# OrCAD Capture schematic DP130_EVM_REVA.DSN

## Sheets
1 S01_COVER_PAGE
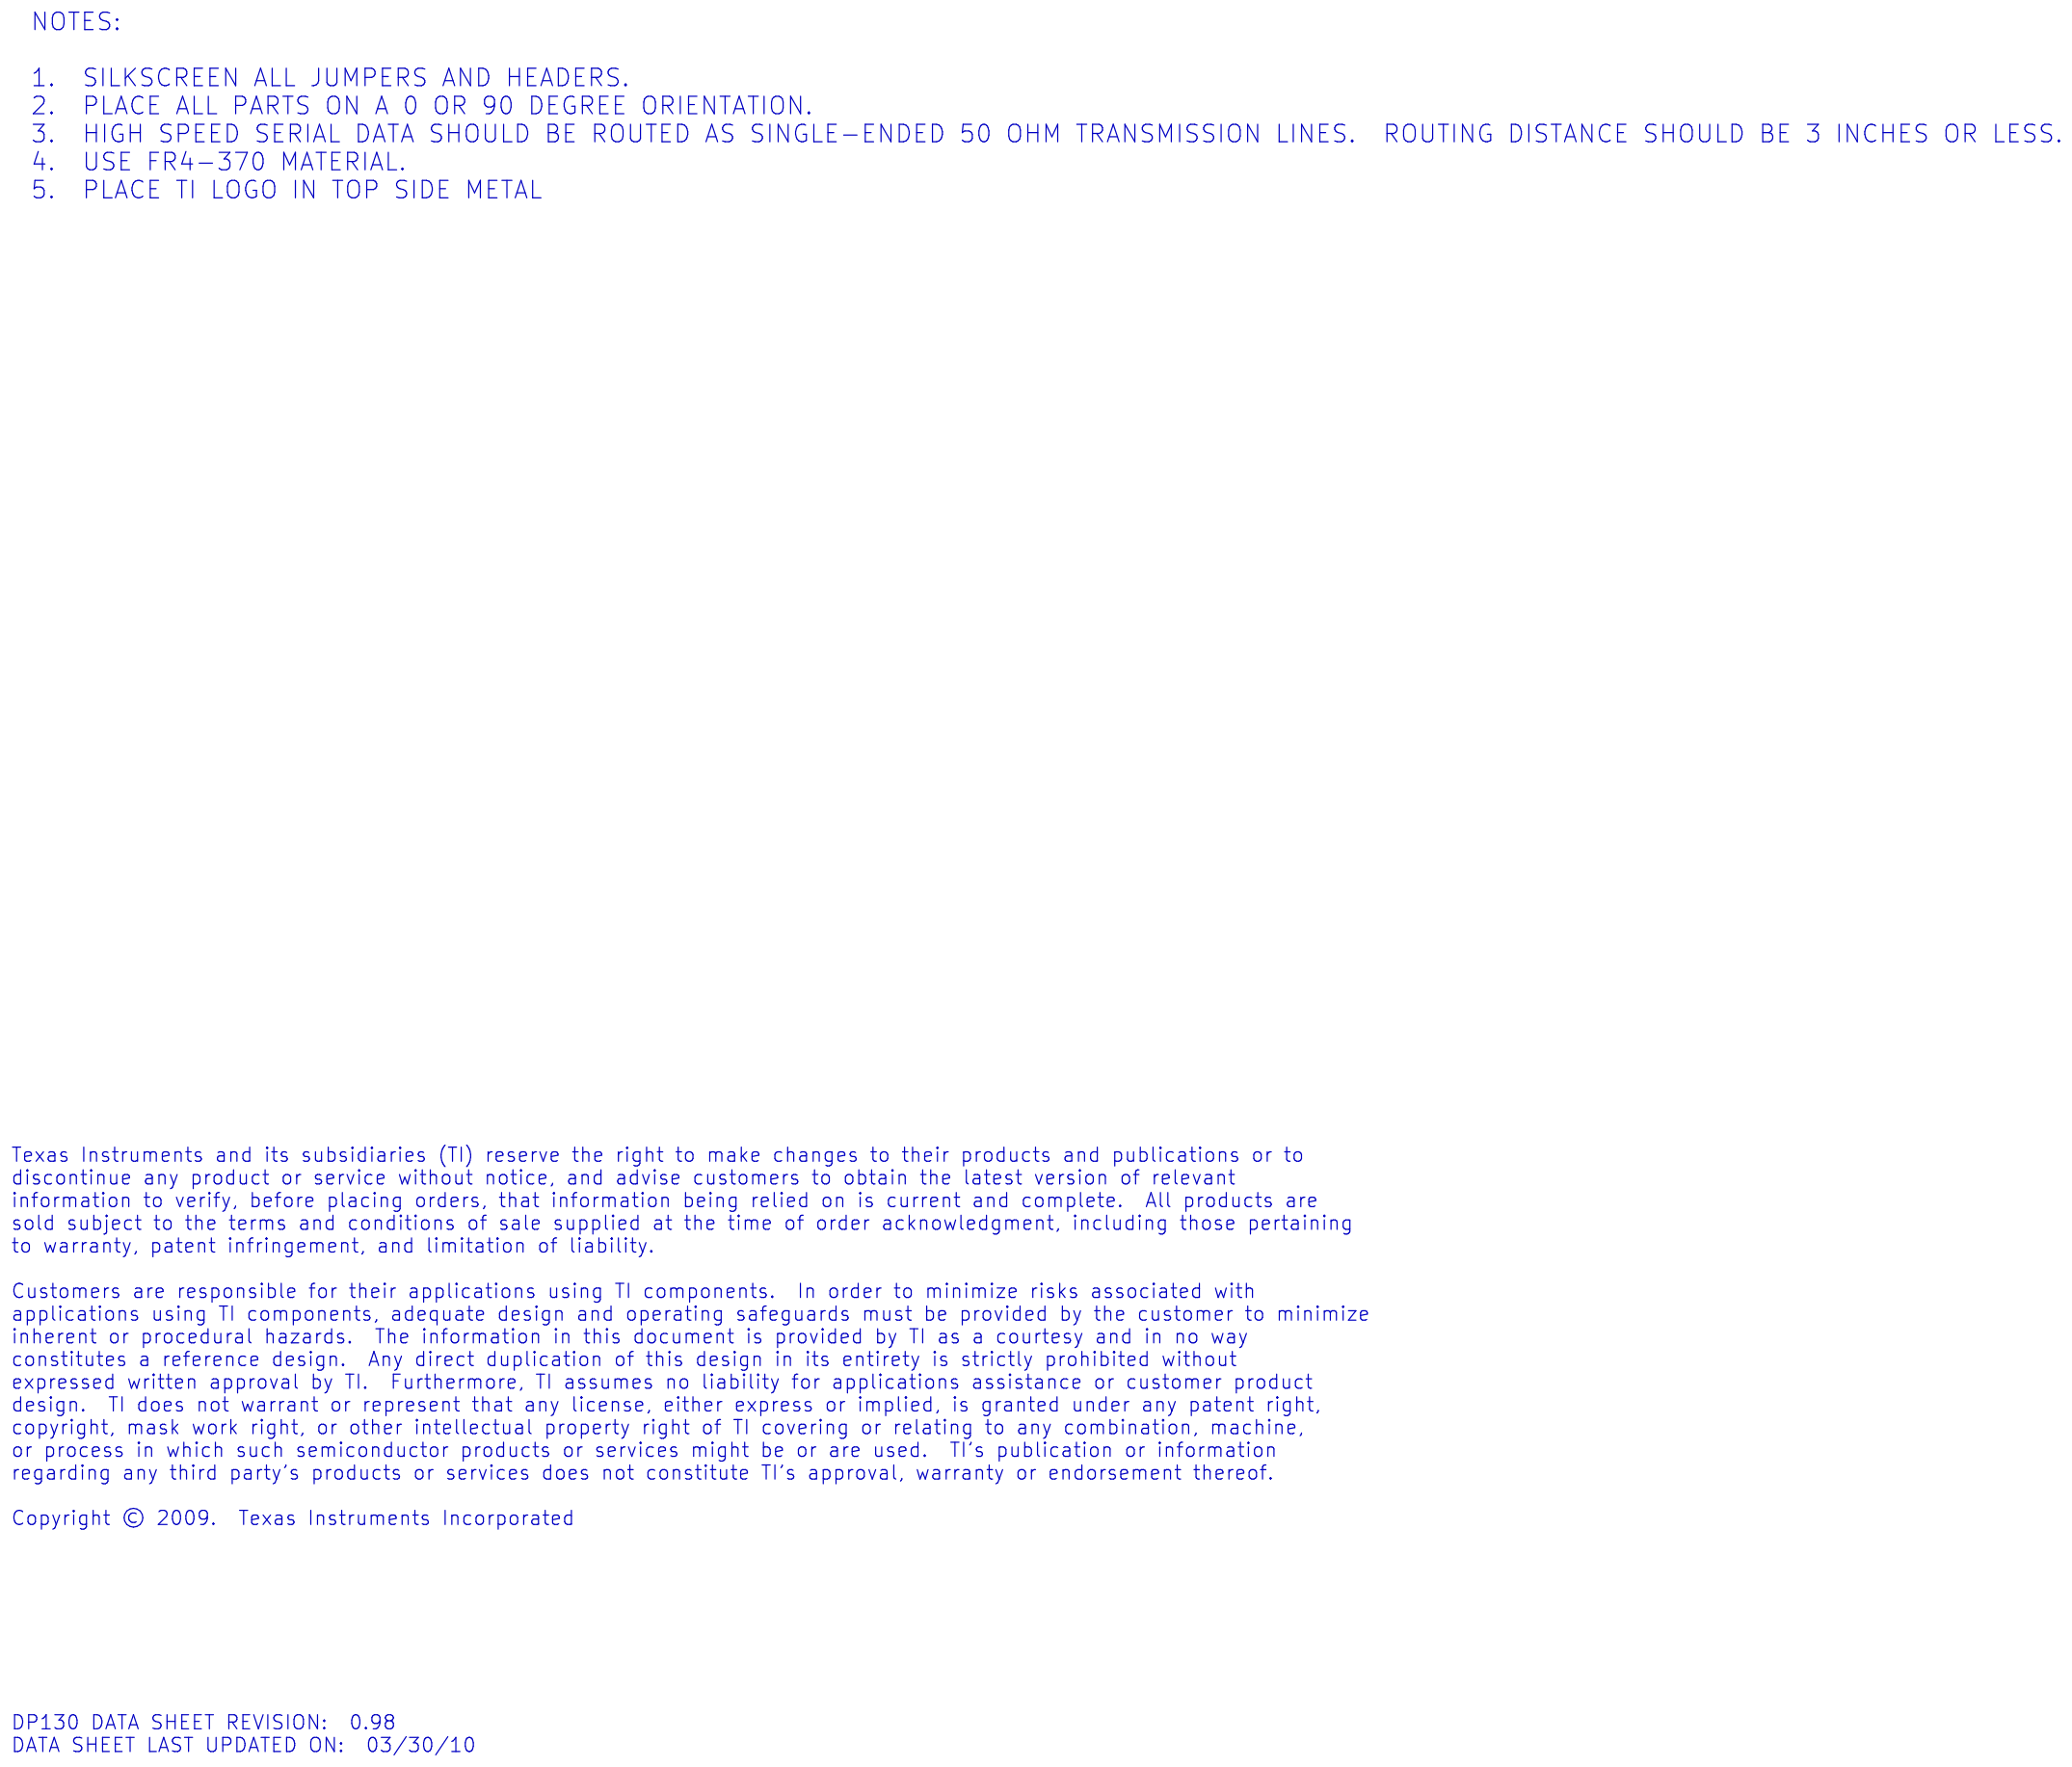
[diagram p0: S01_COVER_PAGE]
2 S02_SOURCE_Connect: size B; note: 6516396
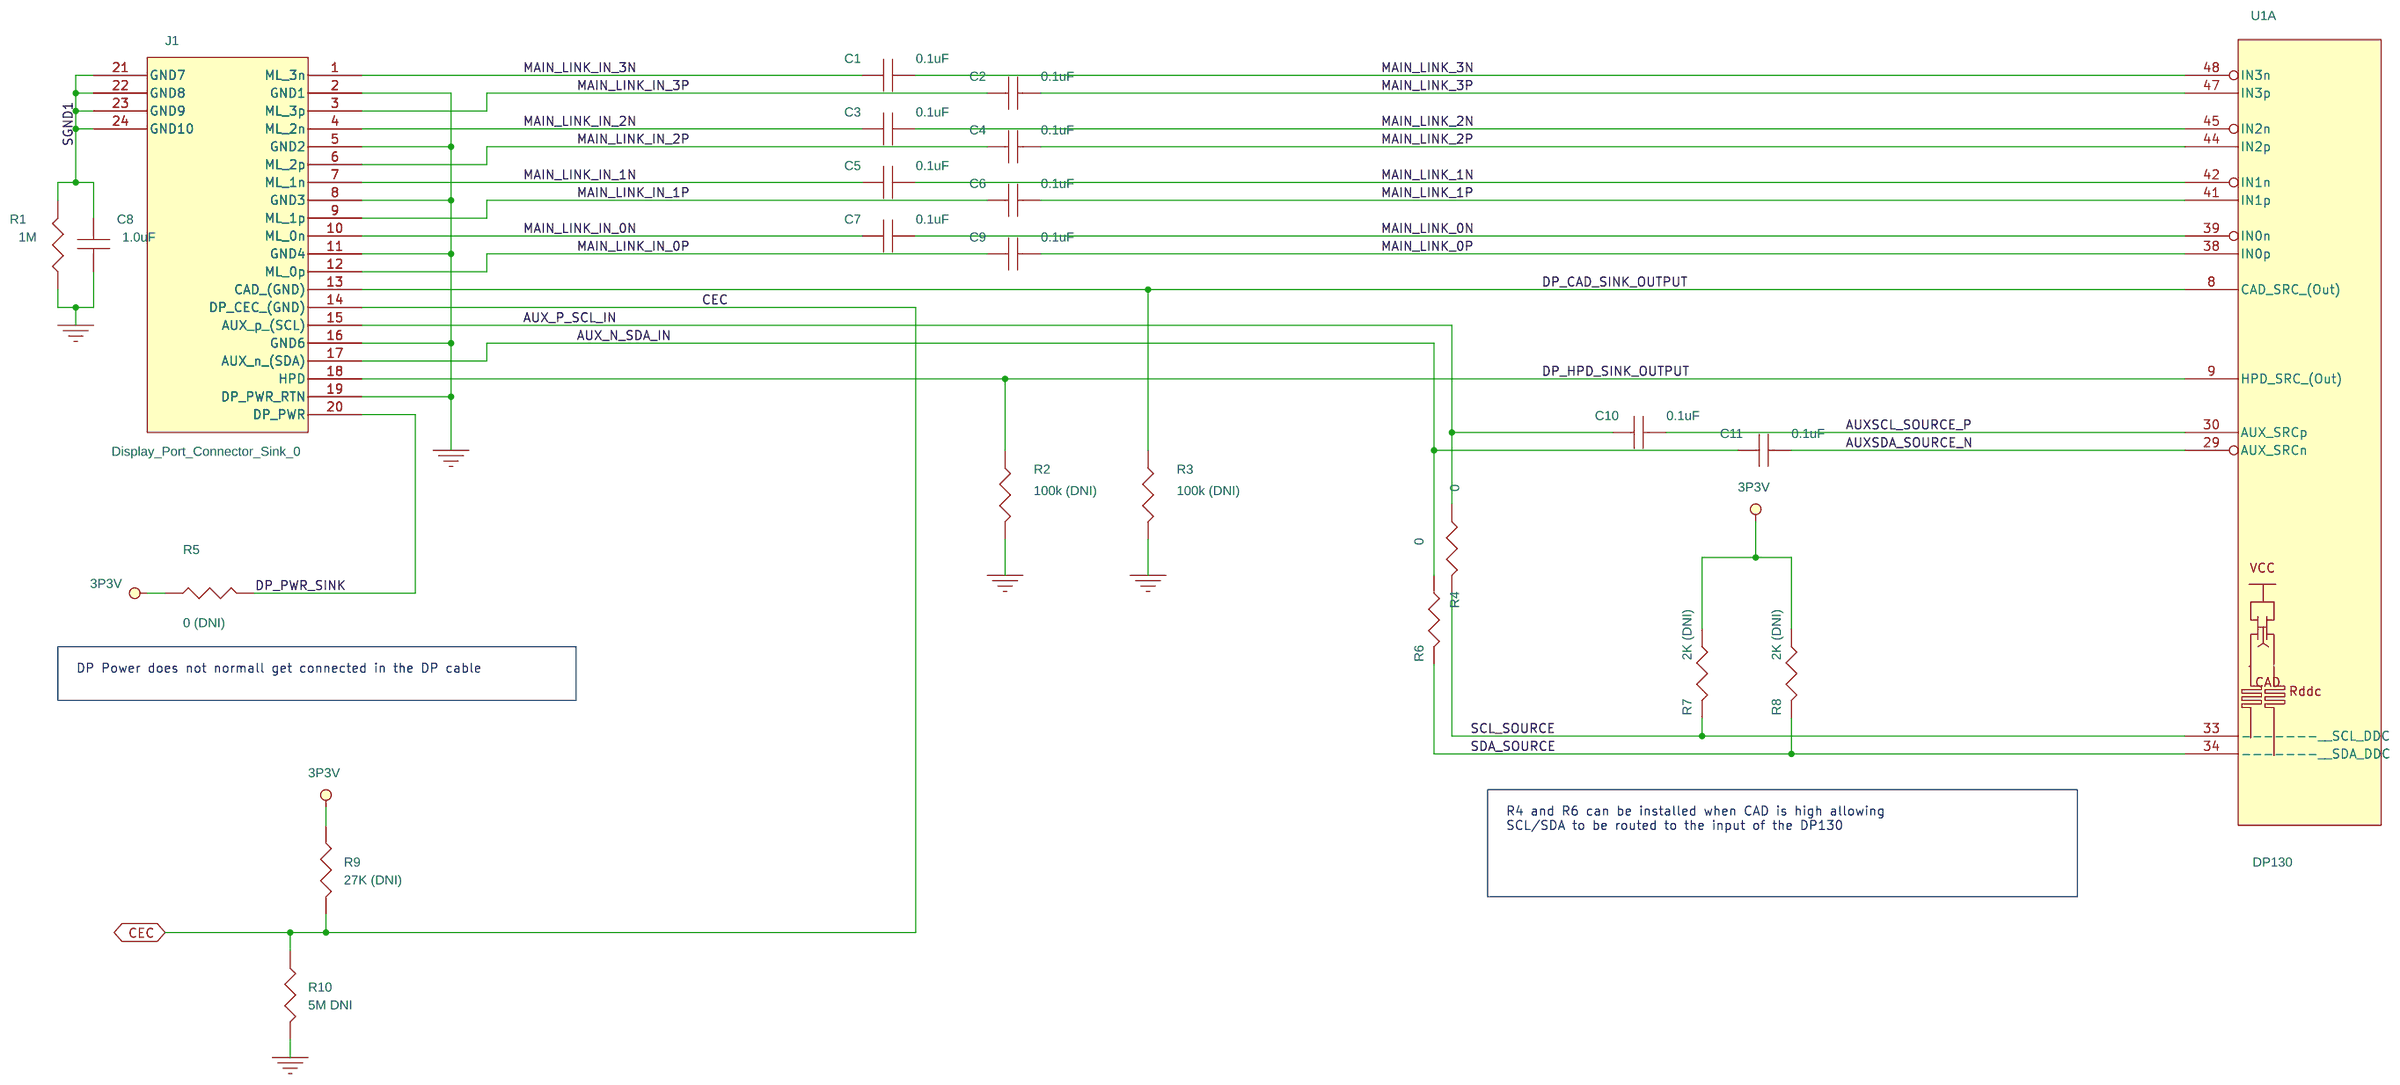
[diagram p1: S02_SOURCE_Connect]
3 S03_SINK_Connect: size B; note: 6516396
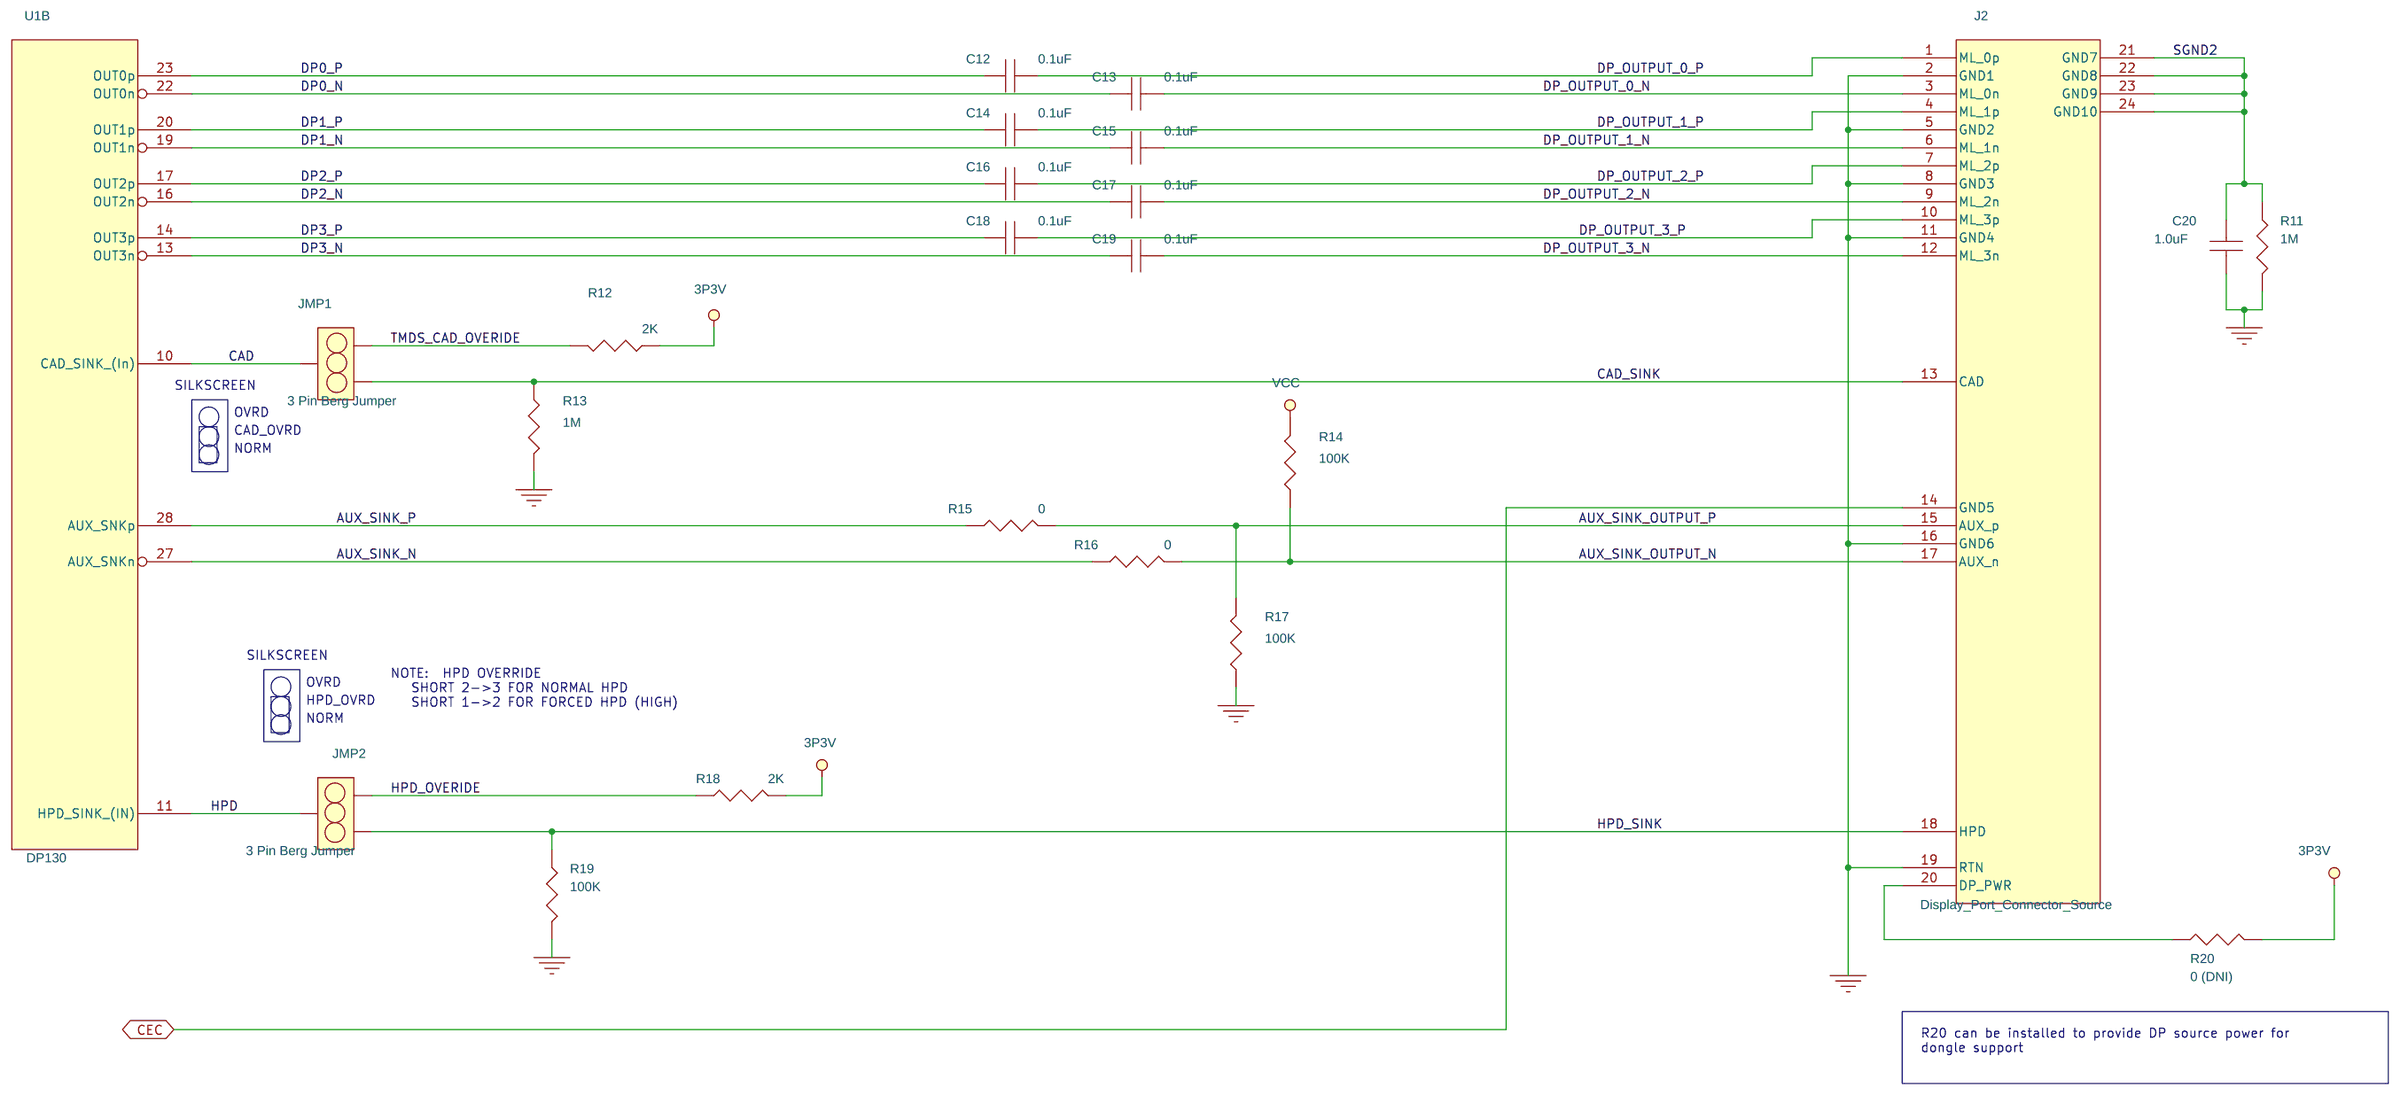
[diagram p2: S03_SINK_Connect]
4 S04_CONTROL: size B; note: 6516396
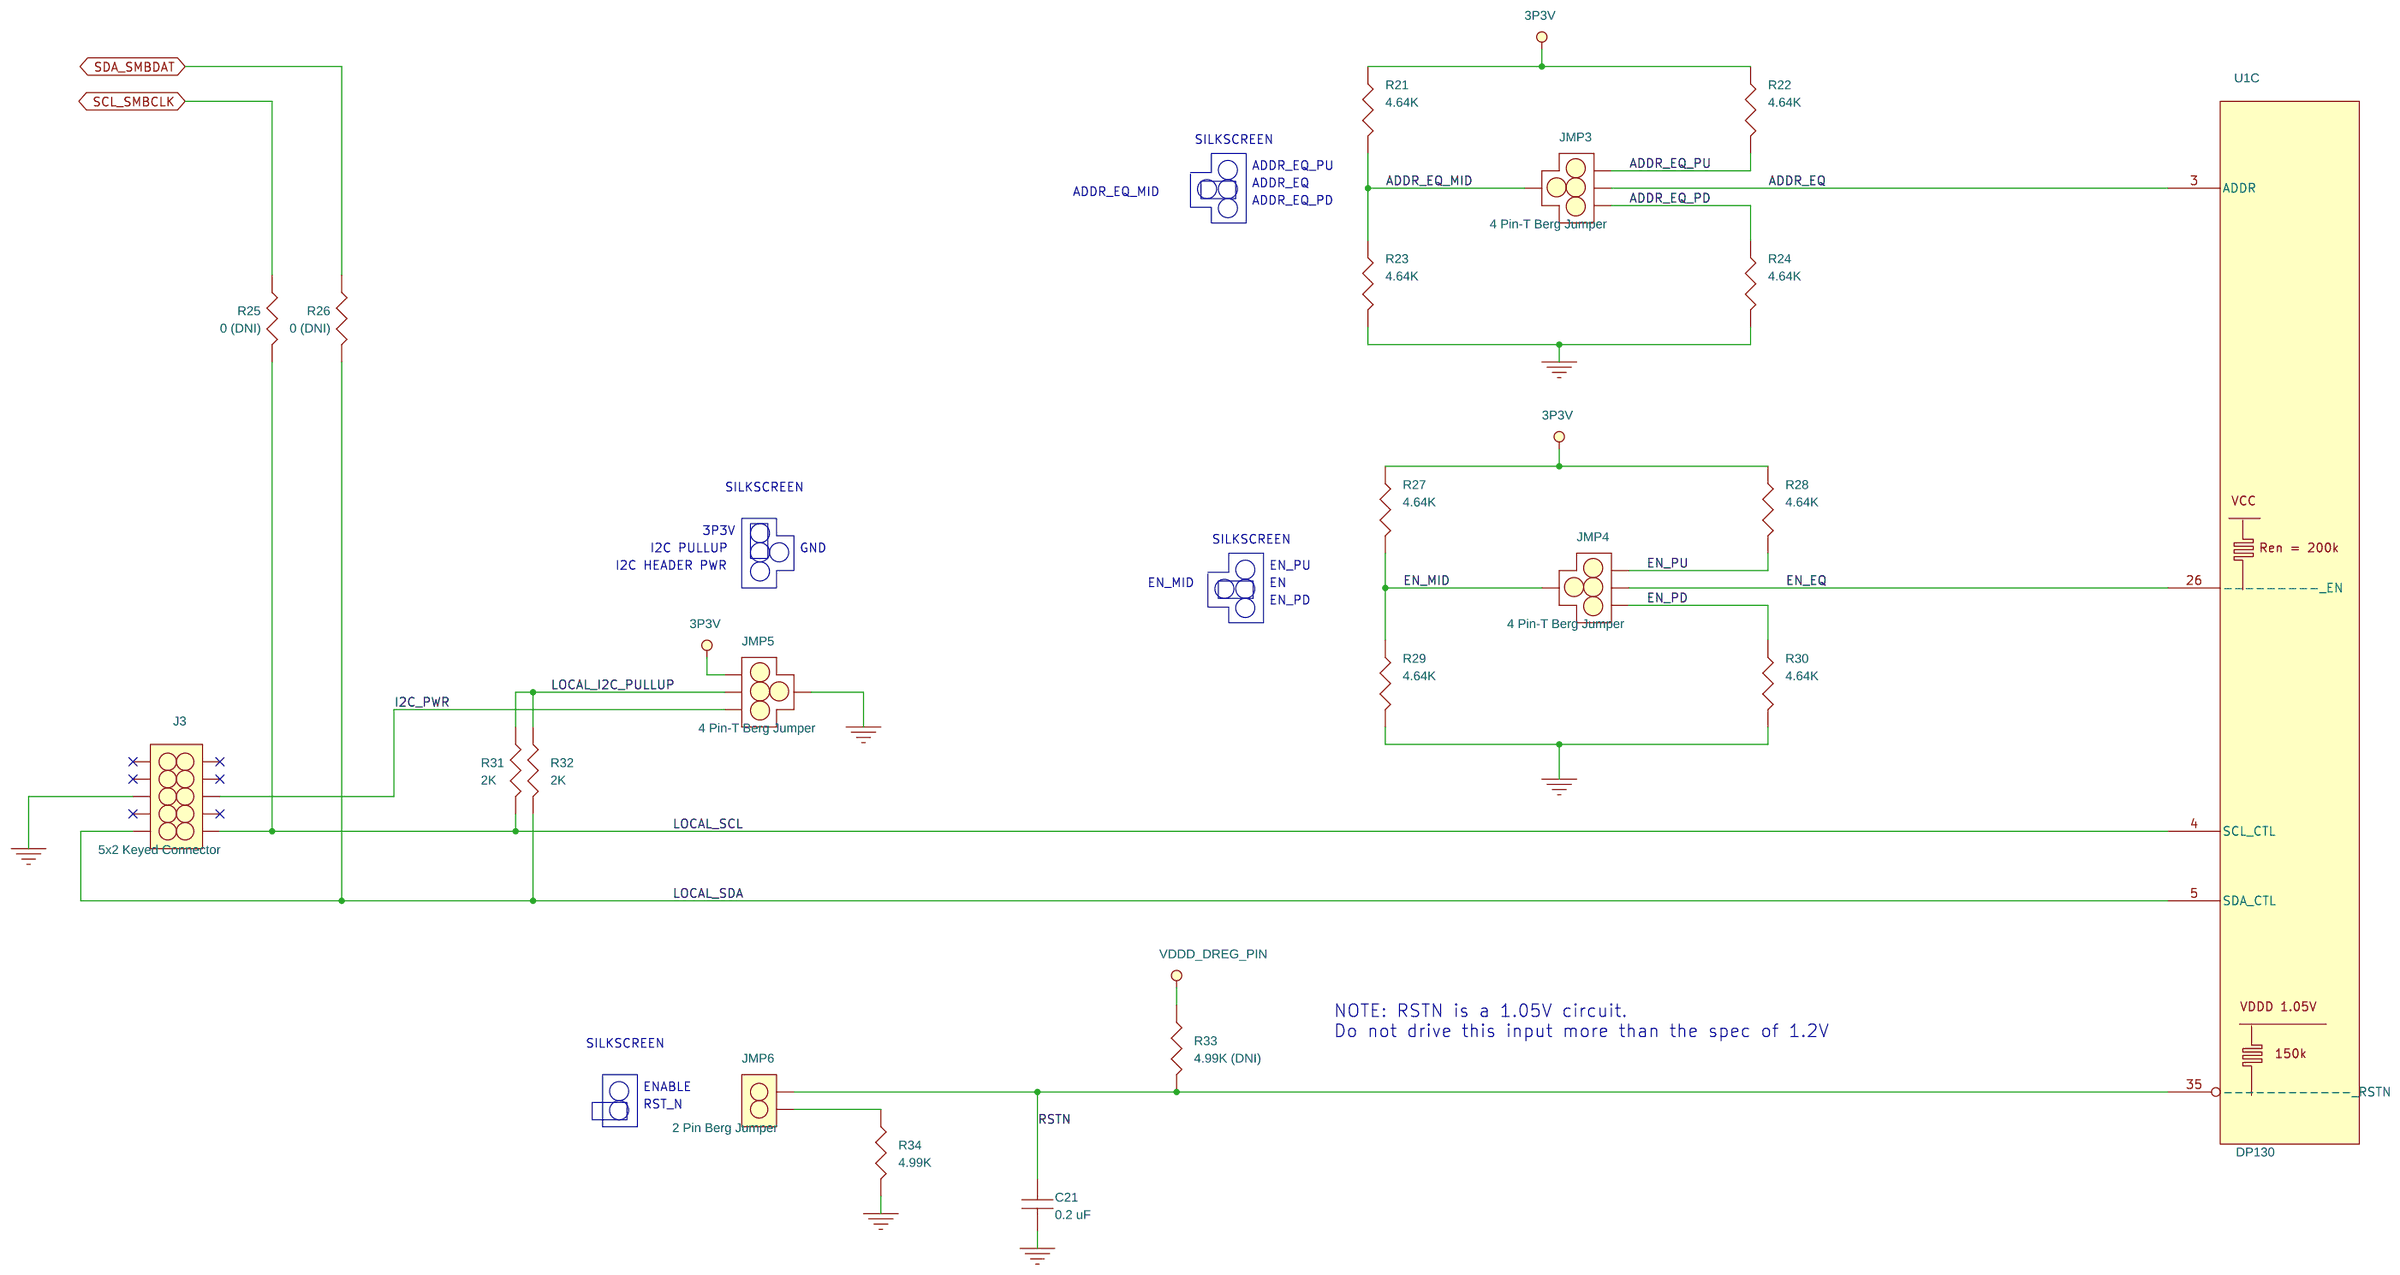
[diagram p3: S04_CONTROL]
5 S05_DEVICE_PWR: size B; note: 6516396
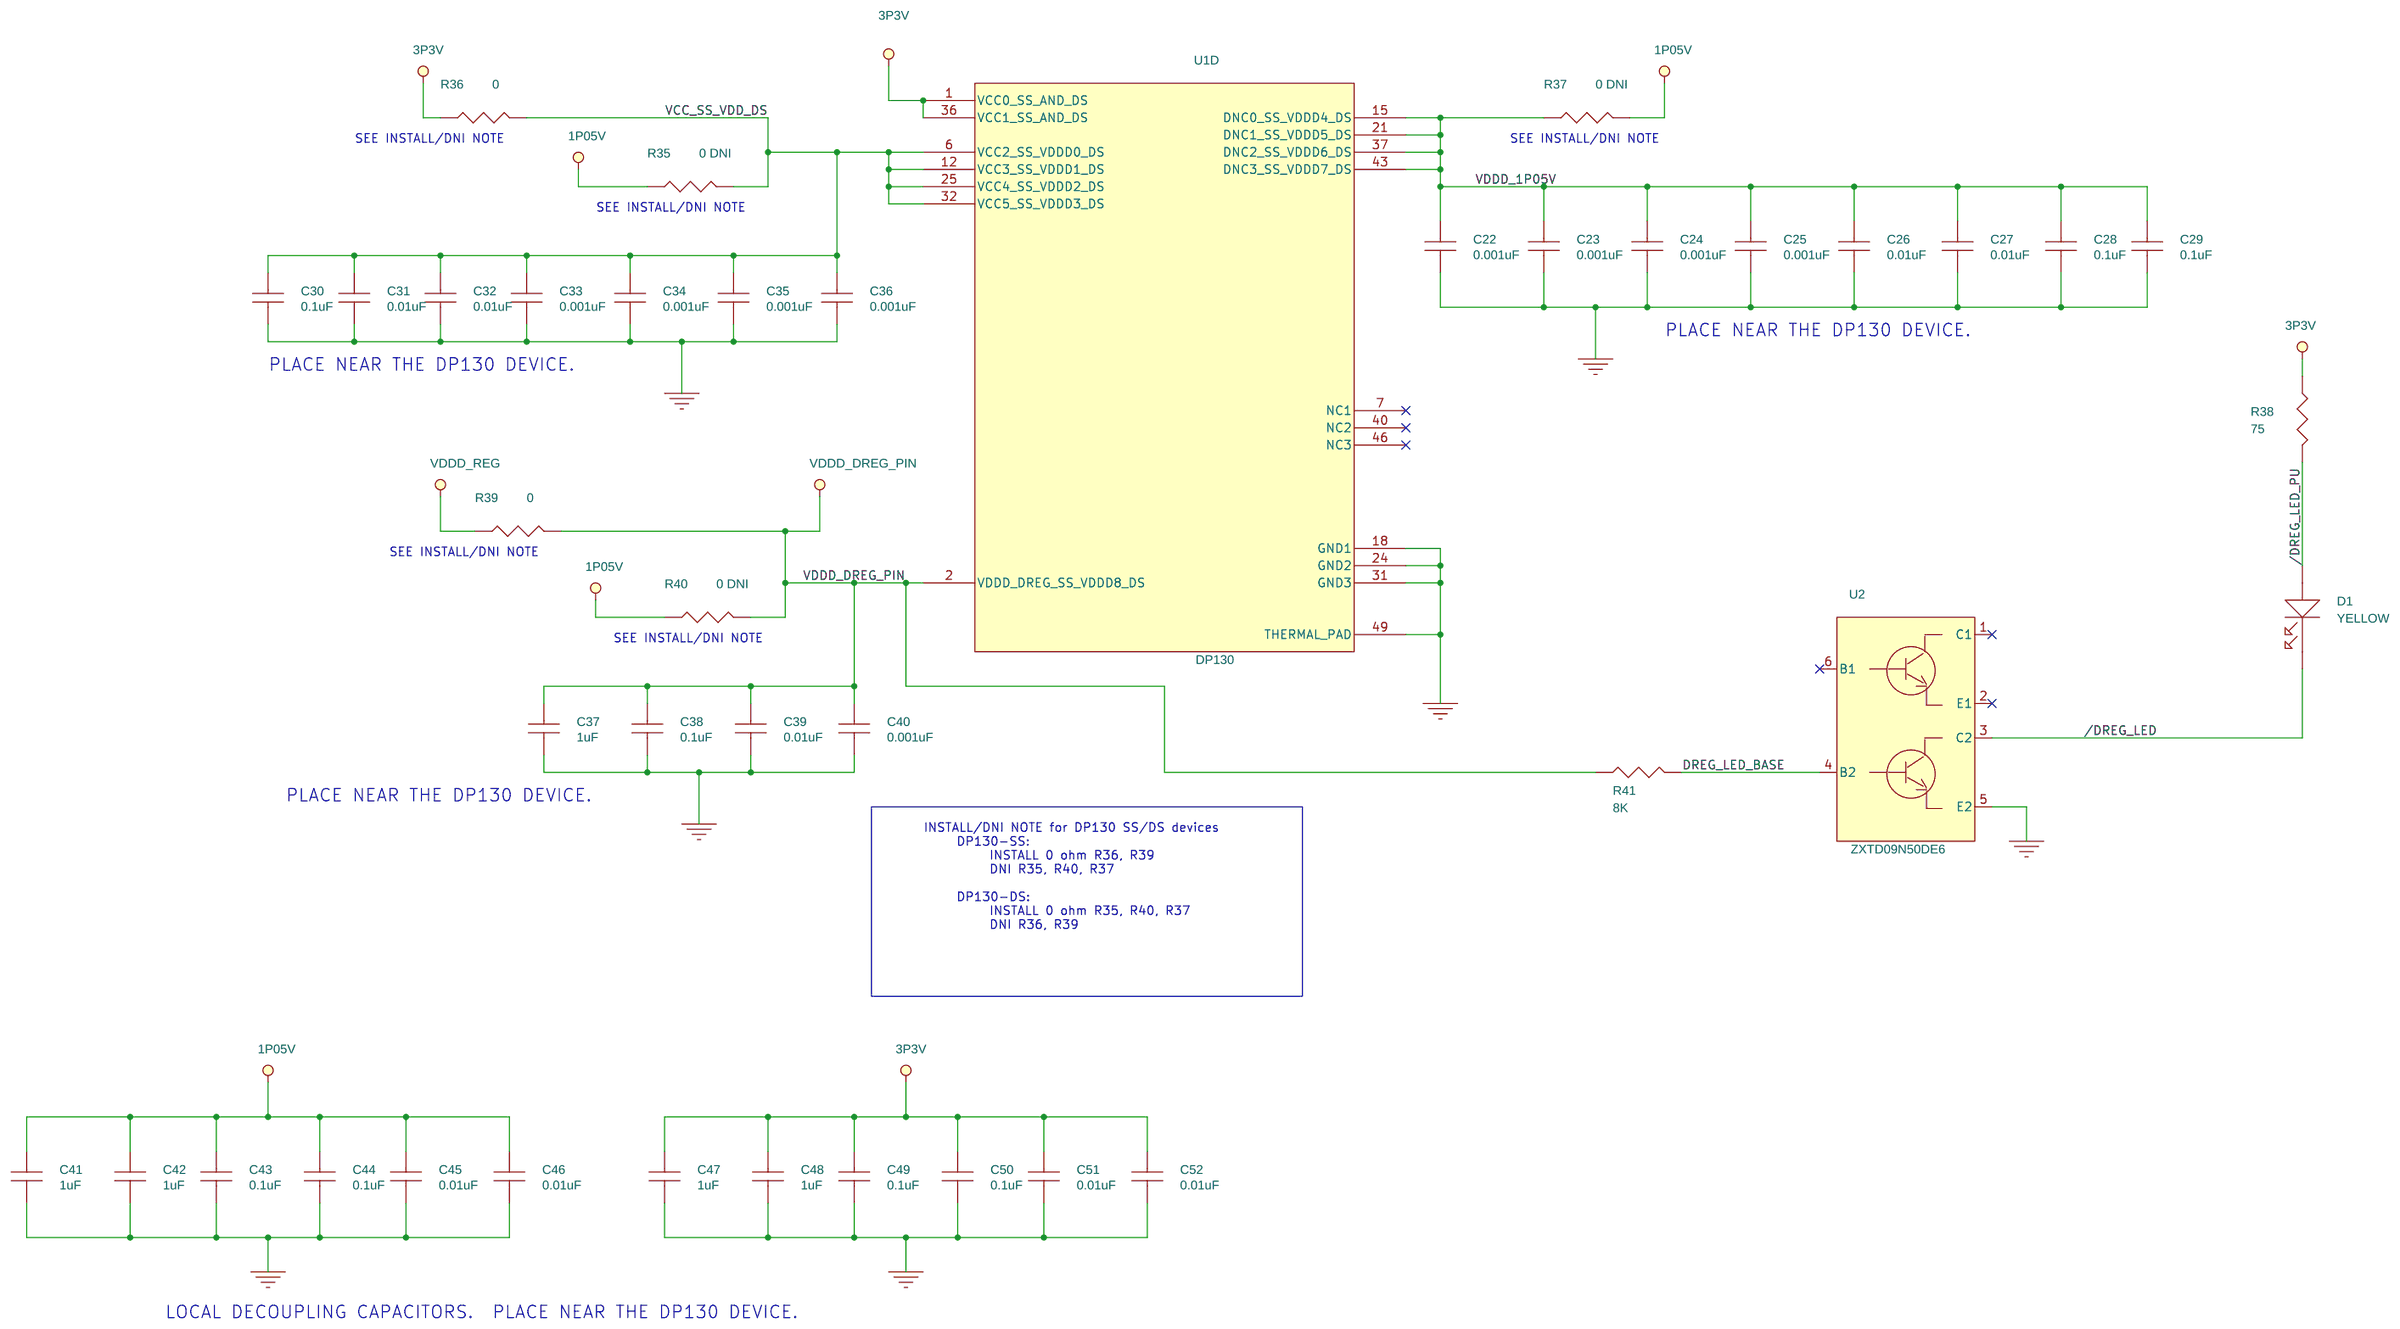
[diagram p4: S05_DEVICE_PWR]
6 S06_EXT_PWR_INTRFC: size B; note: 6516396
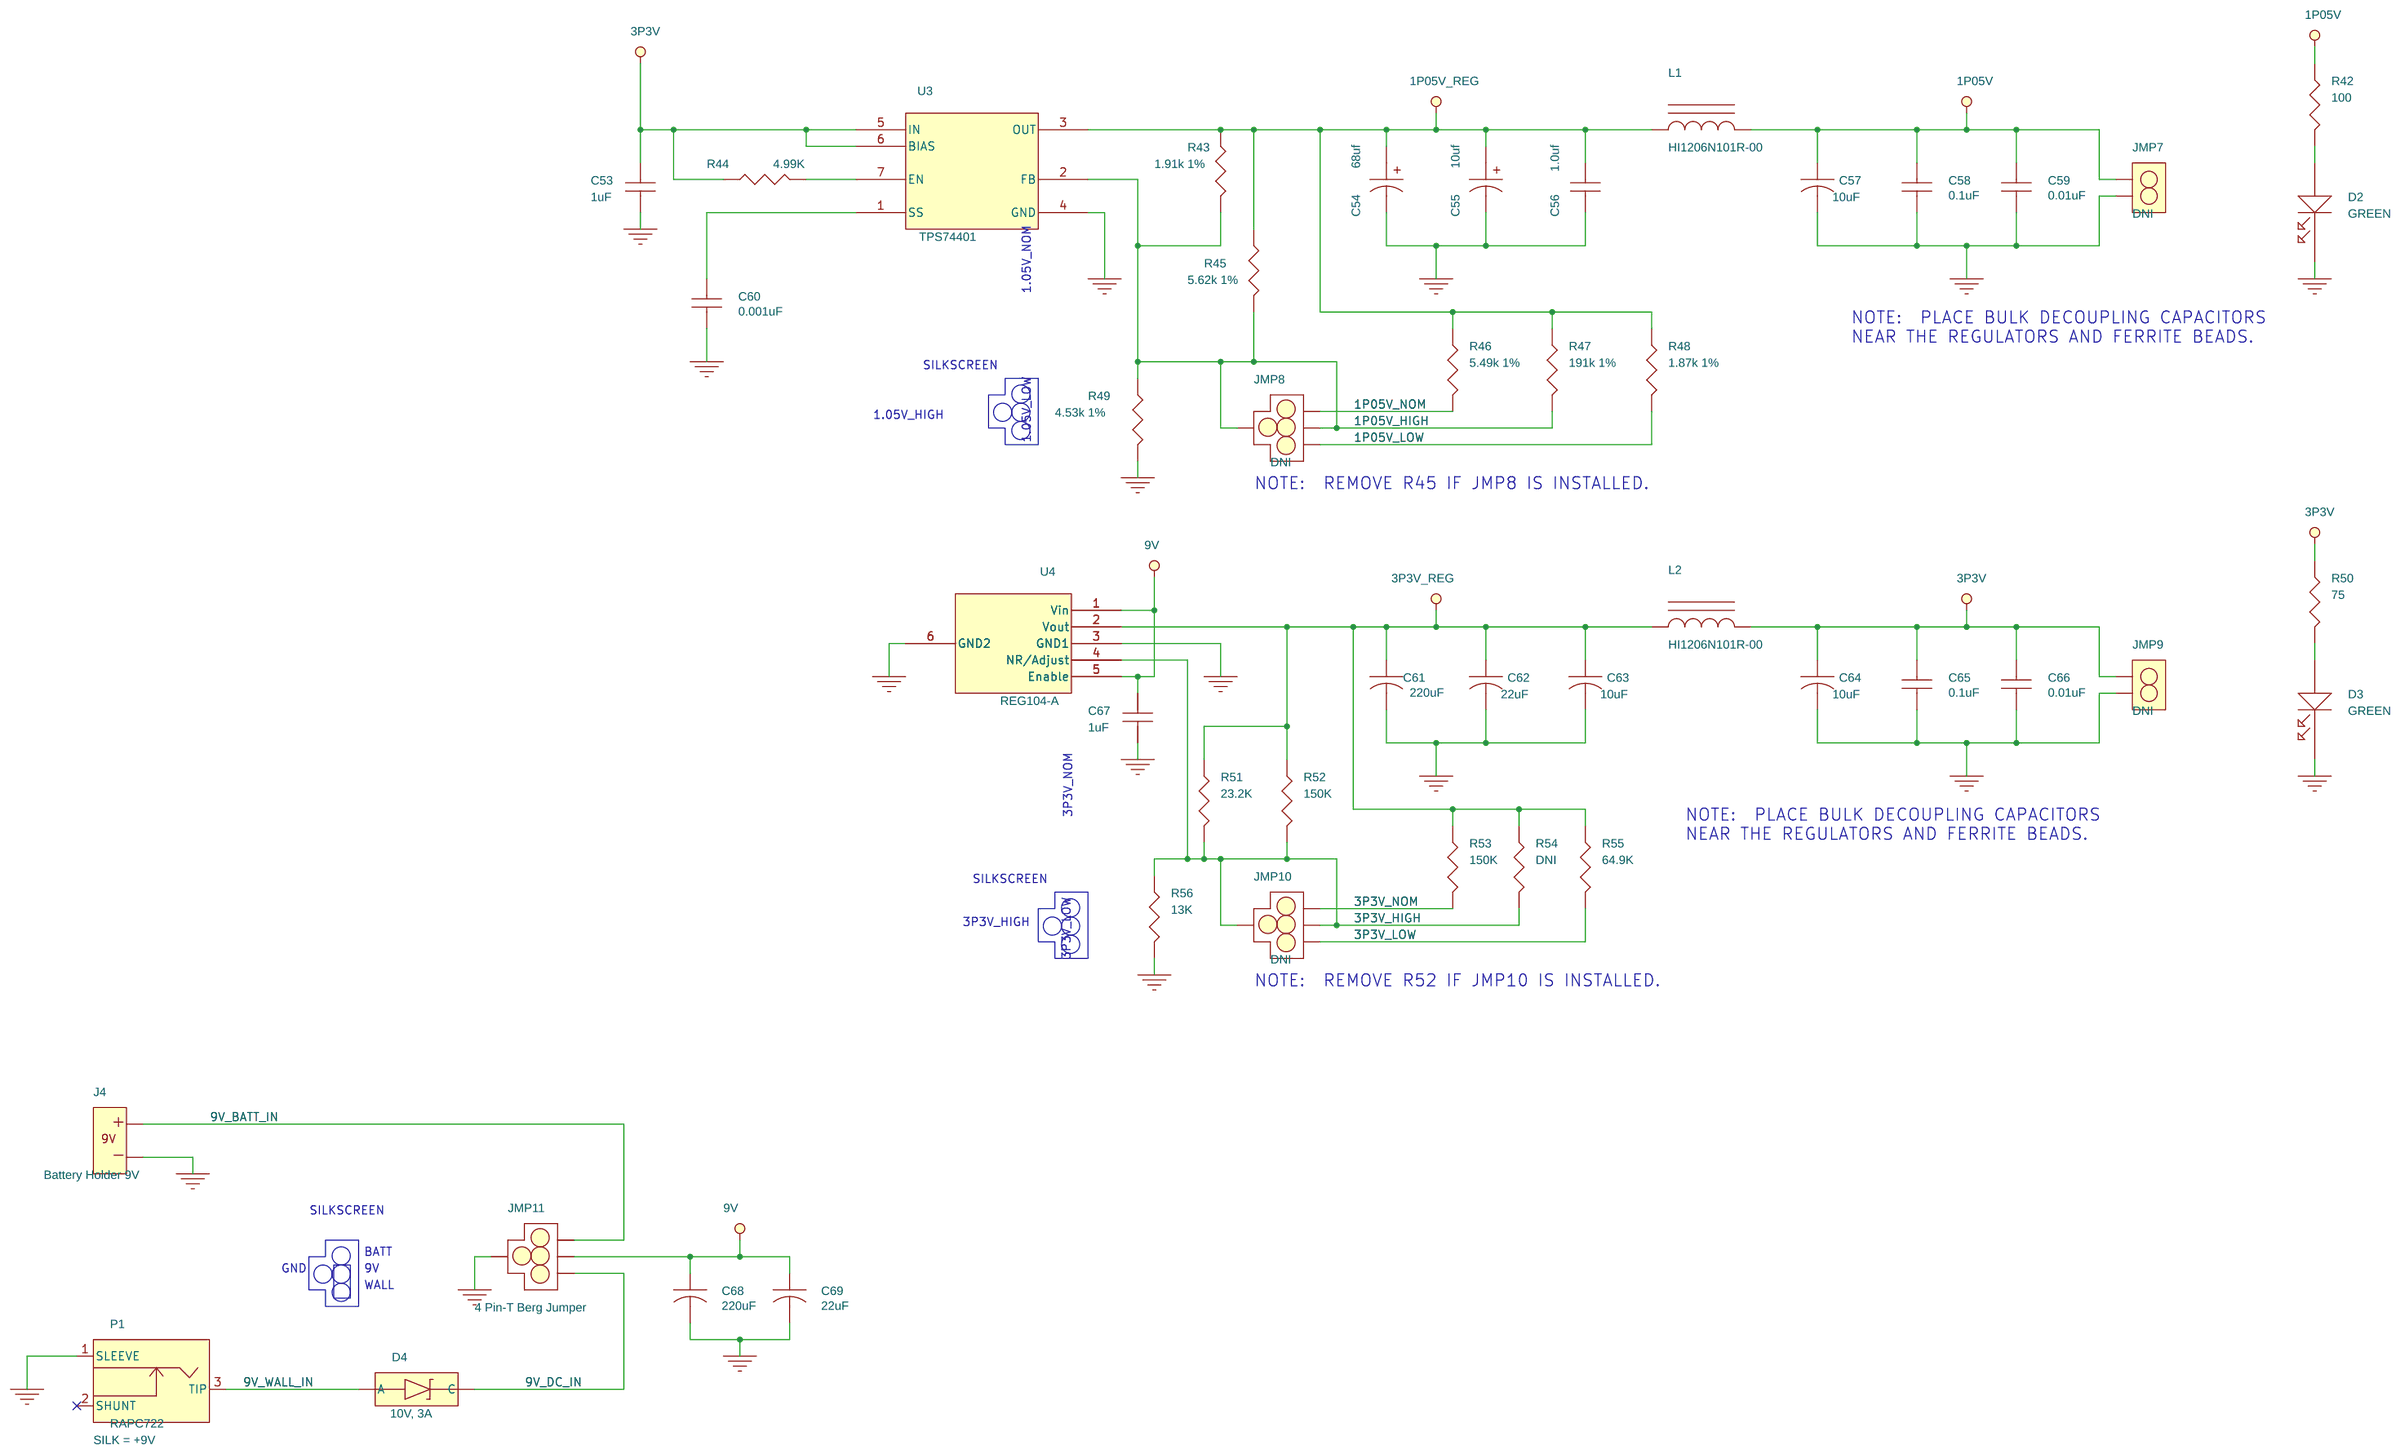
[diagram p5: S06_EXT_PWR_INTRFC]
7 S07 USB I2C 8040: size B; note: 6516396
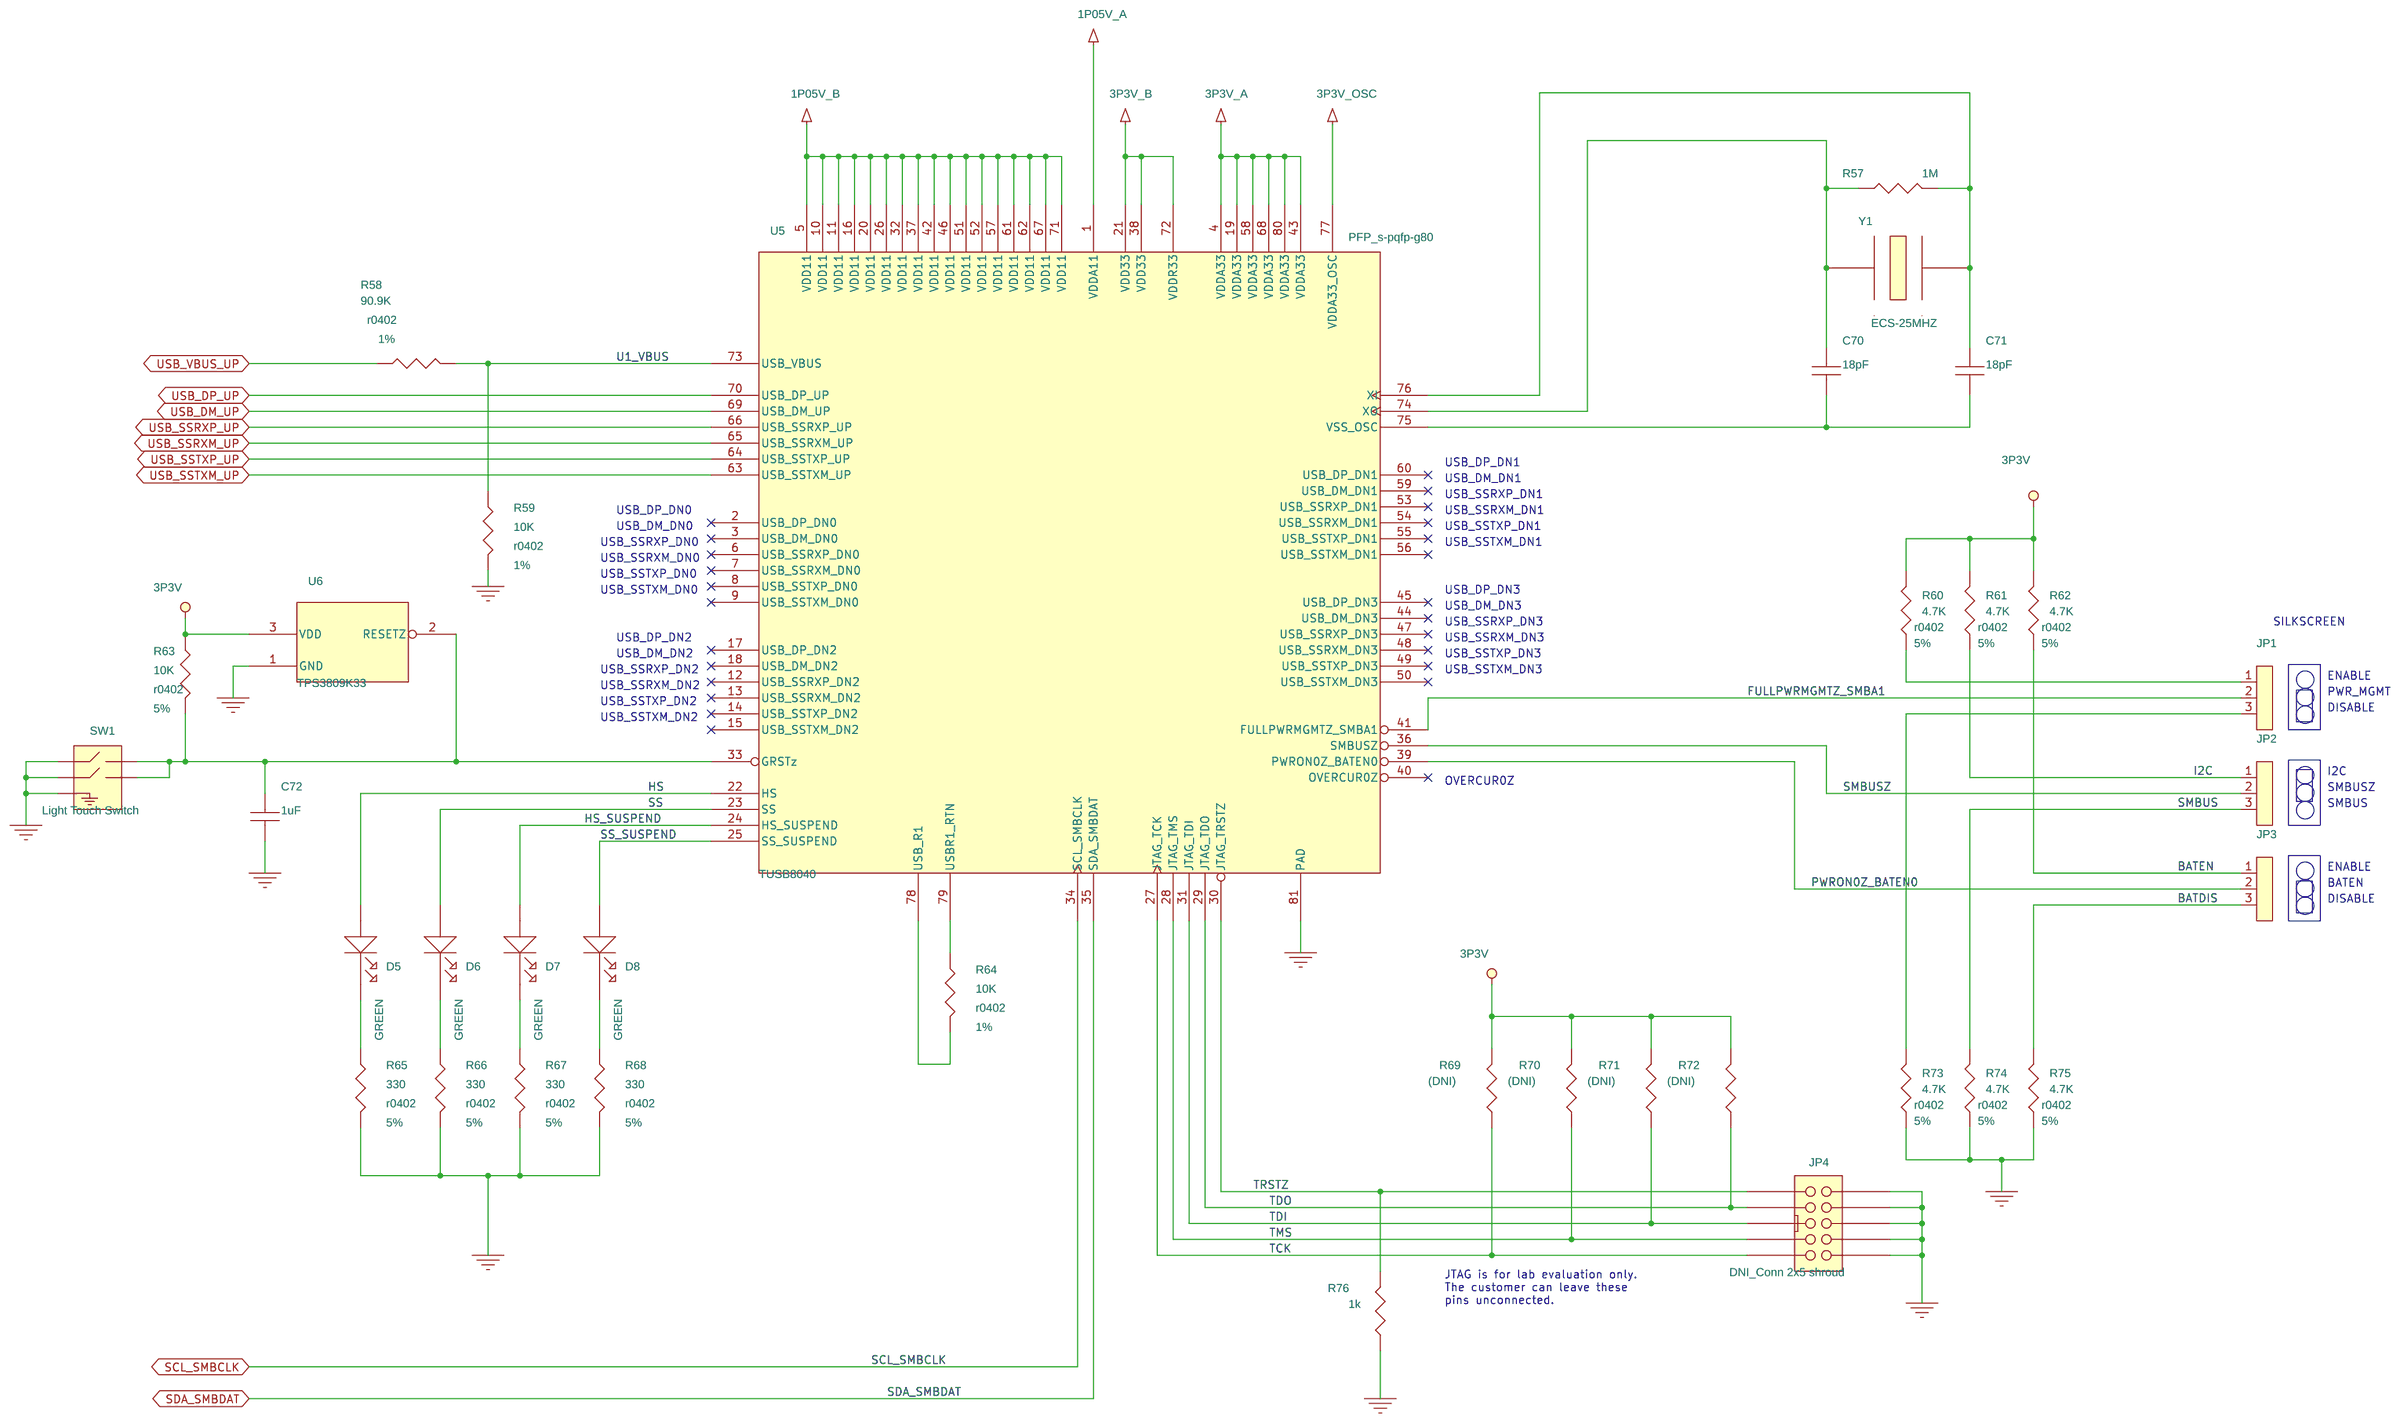
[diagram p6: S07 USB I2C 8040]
8 S08 USB I2C CONNECTORS: size B; note: 6516396
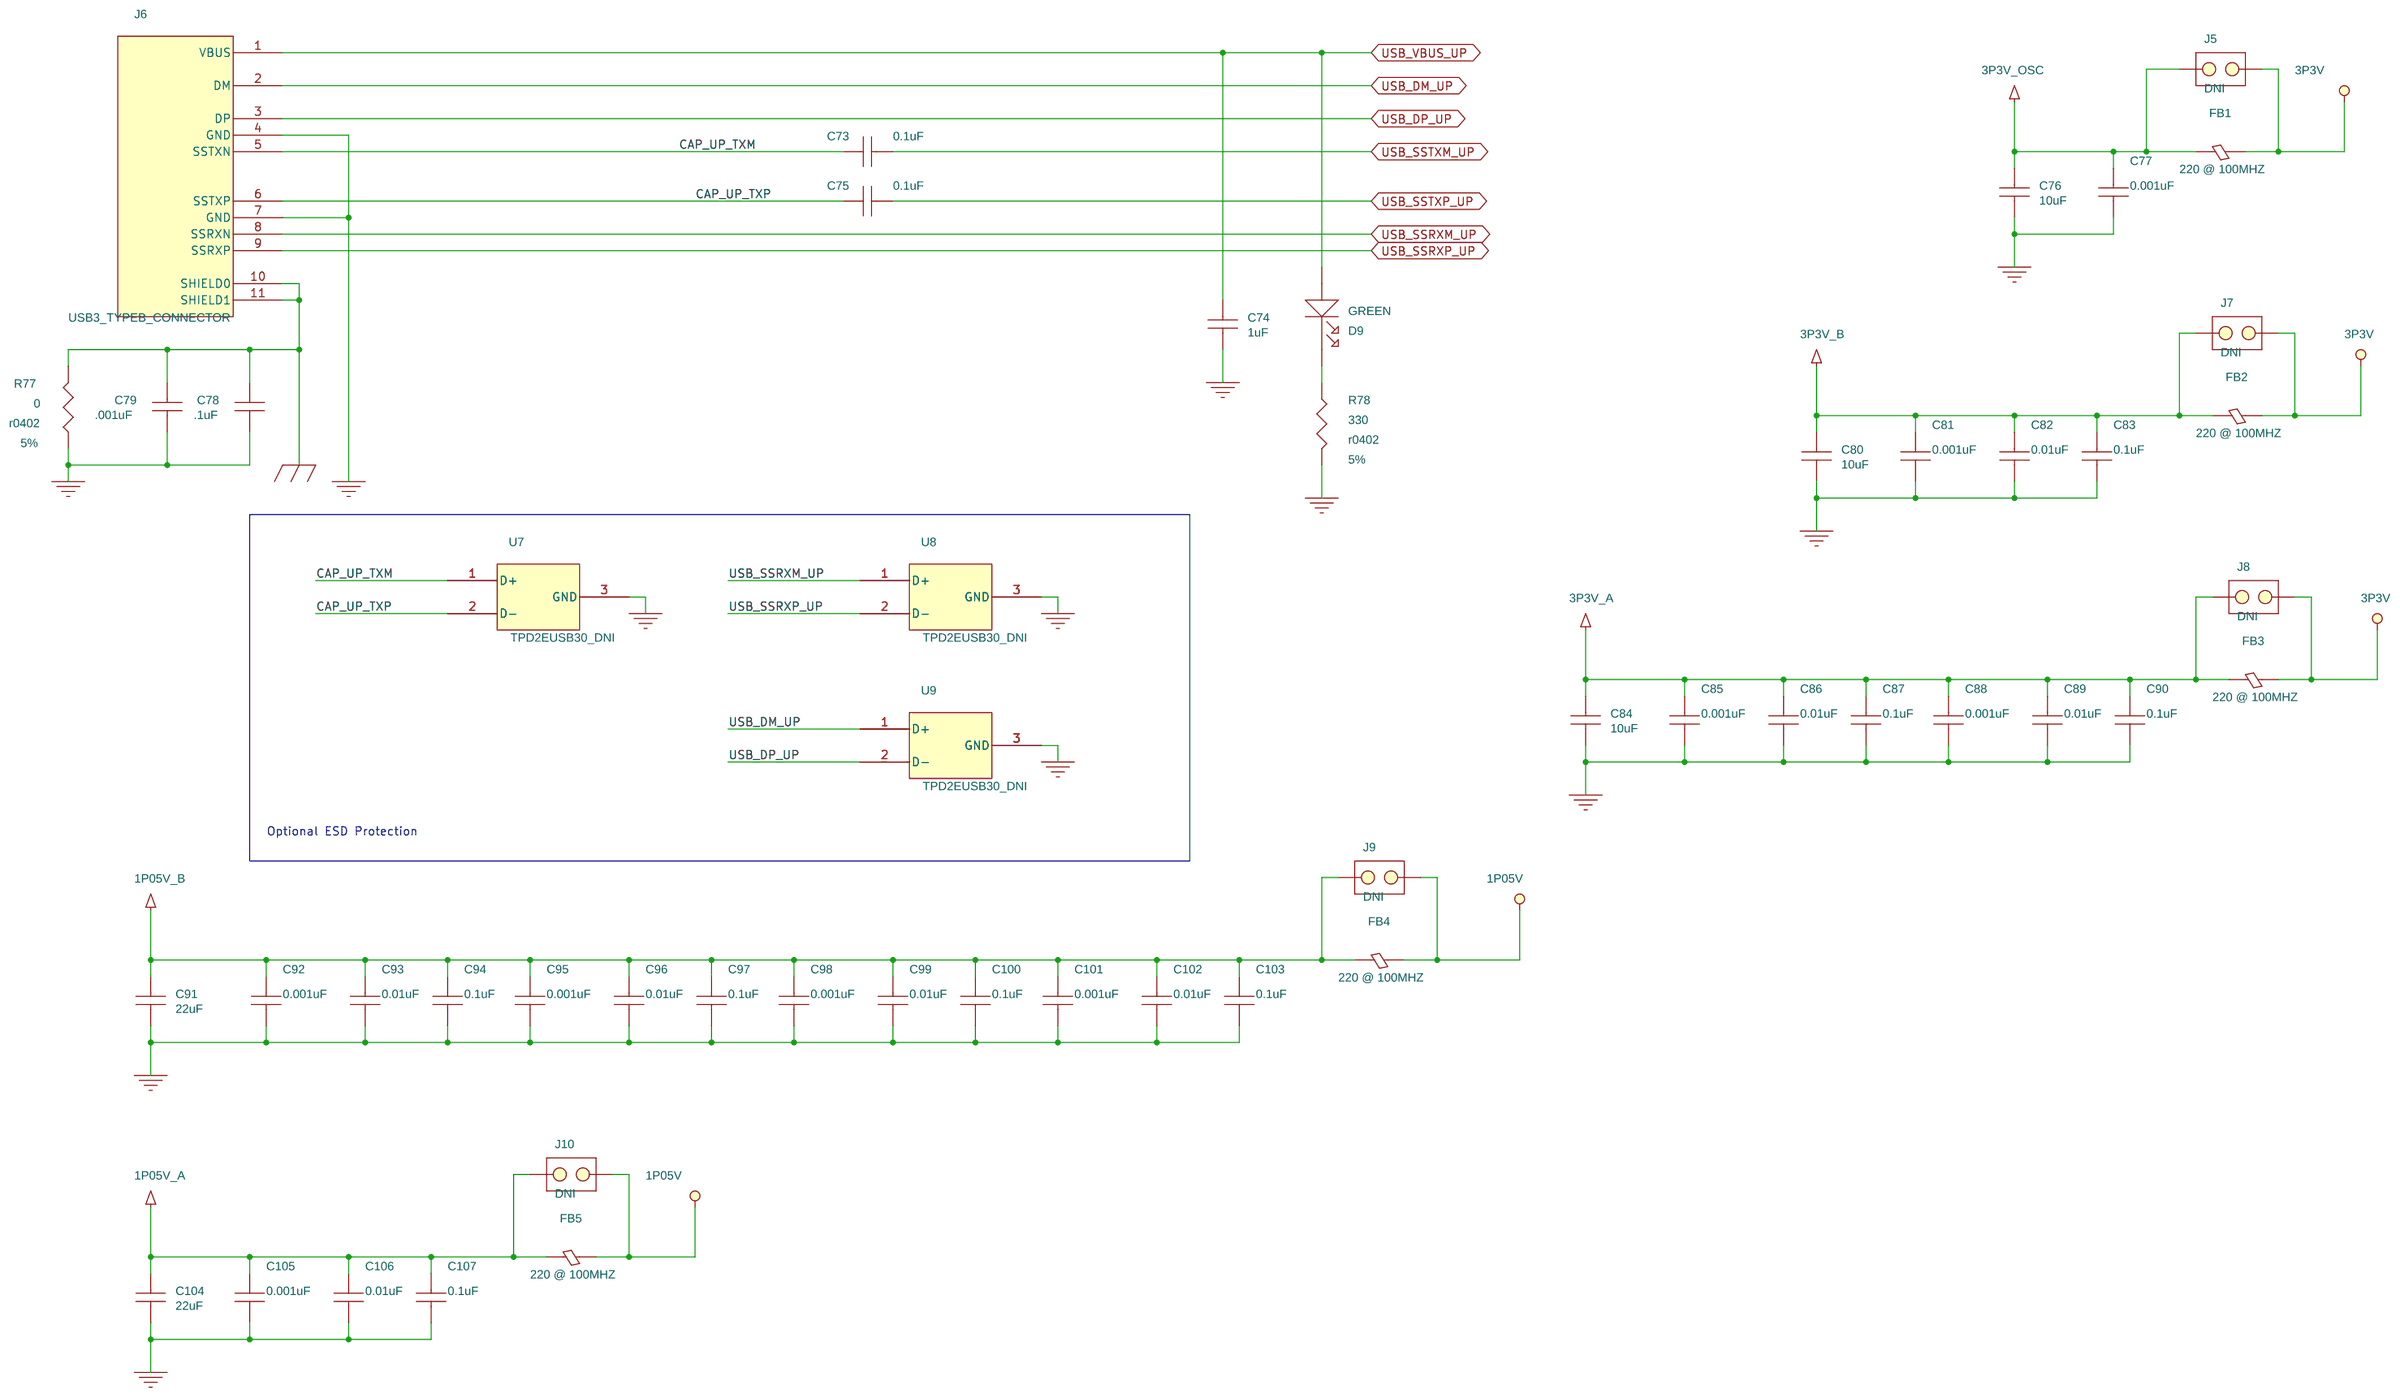
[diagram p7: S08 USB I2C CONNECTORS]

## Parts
sheet S02_SOURCE_Connect
C1  0.1uF  [cc0201]
C2  0.1uF  [cc0201]
C3  0.1uF  [cc0201]
C4  0.1uF  [cc0201]
C5  0.1uF  [cc0201]
C6  0.1uF  [cc0201]
C7  0.1uF  [cc0201]
C8  1.0uF  [cc0603]
C9  0.1uF  [cc0201]
C10  0.1uF  [cc0201]
C11  0.1uF  [cc0201]
J1  Display_Port_Connector_Sink_0  [DISPLAYPORT]
R1  1M  [r0603]
R2  100k (DNI)  [r0402]
R3  100k (DNI)  [r0402]
R4  0  [r0402]
R5  0 (DNI)  [r0402]
R6  0  [r0402]
R7  2K (DNI)  [r0402]
R8  2K (DNI)  [r0402]
R9  27K (DNI)  [r0402]
R10  5M DNI  [r0402]
sheet S03_SINK_Connect
C12  0.1uF  [cc0201]
C13  0.1uF  [cc0201]
C14  0.1uF  [cc0201]
C15  0.1uF  [cc0201]
C16  0.1uF  [cc0201]
C17  0.1uF  [cc0201]
C18  0.1uF  [cc0201]
C19  0.1uF  [cc0201]
C20  1.0uF  [cc0603]
J2  Display_Port_Connector_Source  [DISPLAYPORT]
JMP1  3 Pin Berg Jumper  [berg3]
JMP2  3 Pin Berg Jumper  [berg3]
R11  1M  [r0603]
R12  2K  [r0402]
R13  1M  [r0402]
R14  100K  [r0402]
R15  0  [r0201]
R16  0  [r0201]
R17  100K  [r0402]
R18  2K  [r0402]
R19  100K  [r0402]
R20  0 (DNI)  [r0402]
sheet S04_CONTROL
C21  0.2 uF  [cc0402]
J3  5x2 Keyed Connector  [tyco_5103308-1]
JMP3  4 Pin-T Berg Jumper  [berg2x3tee]
JMP4  4 Pin-T Berg Jumper  [berg2x3tee]
JMP5  4 Pin-T Berg Jumper  [berg2x3tee]
JMP6  2 Pin Berg Jumper  [berg2]
R21  4.64K  [r0603]
R22  4.64K  [r0603]
R23  4.64K  [r0603]
R24  4.64K  [r0603]
R25  0 (DNI)  [r0402]
R26  0 (DNI)  [r0402]
R27  4.64K  [r0603]
R28  4.64K  [r0603]
R29  4.64K  [r0603]
R30  4.64K  [r0603]
R31  2K  [r0402]
R32  2K  [r0402]
R33  4.99K (DNI)  [r0402]
R34  4.99K  [r0402]
U1  DP130  [DP130_socket]  (sections A,B,C,D)
sheet S05_DEVICE_PWR
C22  0.001uF  [cc0402]
C23  0.001uF  [cc0402]
C24  0.001uF  [cc0402]
C25  0.001uF  [cc0402]
C26  0.01uF  [cc0402]
C27  0.01uF  [cc0402]
C28  0.1uF  [cc0402]
C29  0.1uF  [cc0402]
C30  0.1uF  [cc0402]
C31  0.01uF  [cc0402]
C32  0.01uF  [cc0402]
C33  0.001uF  [cc0402]
C34  0.001uF  [cc0402]
C35  0.001uF  [cc0402]
C36  0.001uF  [cc0402]
C37  1uF  [cc0402]
C38  0.1uF  [cc0402]
C39  0.01uF  [cc0402]
C40  0.001uF  [cc0402]
C41  1uF  [cc0402]
C42  1uF  [cc0402]
C43  0.1uF  [cc0402]
C44  0.1uF  [cc0402]
C45  0.01uF  [cc0402]
C46  0.01uF  [cc0402]
C47  1uF  [cc0402]
C48  1uF  [cc0402]
C49  0.1uF  [cc0402]
C50  0.1uF  [cc0402]
C51  0.01uF  [cc0402]
C52  0.01uF  [cc0402]
D1  YELLOW  [led_hsmb_c170dra]
R35  0 DNI  [r0603]
R36  0  [r0603]
R37  0 DNI  [r0603]
R38  75  [r0402]
R39  0  [r0603]
R40  0 DNI  [r0603]
R41  8K  [r0402]
U2  ZXTD09N50DE6  [DDC6]
sheet S06_EXT_PWR_INTRFC
C53  1uF  [cc0402]
C54  68uf  [cc7343]
C55  10uf  [cc7343]
C56  1.0uf  [cc1206]
C57  10uF  [cc7343]
C58  0.1uF  [cc0402]
C59  0.01uF  [cc0402]
C60  0.001uF  [cc0402]
C61  220uF  [cc7343]
C62  22uF  [cc7343]
C63  10uF  [cc7343]
C64  10uF  [cc7343]
C65  0.1uF  [cc0402]
C66  0.01uF  [cc0402]
C67  1uF  [cc0402]
C68  220uF  [cc7343]
C69  22uF  [cc7343]
D2  GREEN  [led_hsmb_c170dra]
D3  GREEN  [led_hsmb_c170dra]
D4  10V, 3A  [SOD323]
J4  Battery Holder 9V  [9v_battery]
JMP7  DNI  [berg2]
JMP8  DNI  [berg2x3tee]
JMP9  DNI  [berg2]
JMP10  DNI  [berg2x3tee]
JMP11  4 Pin-T Berg Jumper  [berg2x3tee]
L1  HI1206N101R-00  [cc1210]
L2  HI1206N101R-00  [cc1210]
P1  RAPC722  [con_rapc722_jack_thvt_3]
R42  100  [r0402]
R43  1.91k 1%  [r0603]
R44  4.99K  [r0603]
R45  5.62k 1%  [r0603]
R46  5.49k 1%  [r0603]
R47  191k 1%  [r0603]
R48  1.87k 1%  [r0603]
R49  4.53k 1%  [r0603]
R50  75  [r0402]
R51  23.2K  [r0603]
R52  150K  [r0603]
R53  150K  [r0603]
R54  DNI  [r0603]
R55  64.9K  [r0603]
R56  13K  [r0603]
U3  TPS74401  [KTW7]
U4  REG104-A  [DCQ_R-PDSO-G6]
sheet S07 USB I2C 8040
C70  18pF  [cc0402]
C71  18pF  [cc0402]
C72  1uF  [cc0402]
D5  GREEN  [r0603]
D6  GREEN  [r0603]
D7  GREEN  [r0603]
D8  GREEN  [r0603]
JP1  Head 1x3  [berg1x3]
JP2  Head 1x3  [berg1x3]
JP3  Head 1x3  [berg1x3]
JP4  DNI_Conn 2x5 shroud  [tyco_5103308-1]
R57  1M  [r0402]
R58  90.9K  [r0402]
R59  10K  [r0402]
R60  4.7K  [r0402]
R61  4.7K  [r0402]
R62  4.7K  [r0402]
R63  10K  [r0402]
R64  10K  [r0402]
R65  330  [r0402]
R66  330  [r0402]
R67  330  [r0402]
R68  330  [r0402]
R69  (DNI)  [r0402]
R70  (DNI)  [r0402]
R71  (DNI)  [r0402]
R72  (DNI)  [r0402]
R73  4.7K  [r0402]
R74  4.7K  [r0402]
R75  4.7K  [r0402]
R76  1k  [r0402]
SW1  Light Touch Switch  [sw_evq-pbc05r]
U5  TUSB8040  [PFP_s-pqfp-g80]
U6  TPS3809K33  [dbv3]
Y1  ECS-25MHZ  [ECX-53B]
sheet S08 USB I2C CONNECTORS
C73  0.1uF  [cc0201]
C74  1uF  [cc0805]
C75  0.1uF  [cc0201]
C76  10uF  [cc0805]
C77  0.001uF  [cc0402]
C78  .1uF  [cc0805]
C79  .001uF  [cc0805]
C80  10uF  [cc0805]
C81  0.001uF  [cc0402]
C82  0.01uF  [cc0402]
C83  0.1uF  [cc0402]
C84  10uF  [cc0805]
C85  0.001uF  [cc0402]
C86  0.01uF  [cc0402]
C87  0.1uF  [cc0402]
C88  0.001uF  [cc0402]
C89  0.01uF  [cc0402]
C90  0.1uF  [cc0402]
C91  22uF  [cc0805]
C92  0.001uF  [cc0402]
C93  0.01uF  [cc0402]
C94  0.1uF  [cc0402]
C95  0.001uF  [cc0402]
C96  0.01uF  [cc0402]
C97  0.1uF  [cc0402]
C98  0.001uF  [cc0402]
C99  0.01uF  [cc0402]
C100  0.1uF  [cc0402]
C101  0.001uF  [cc0402]
C102  0.01uF  [cc0402]
C103  0.1uF  [cc0402]
C104  22uF  [cc0805]
C105  0.001uF  [cc0402]
C106  0.01uF  [cc0402]
C107  0.1uF  [cc0402]
D9  GREEN  [r0603]
FB1  220 @ 100MHZ  [cc0603]
FB2  220 @ 100MHZ  [cc0603]
FB3  220 @ 100MHZ  [cc0603]
FB4  220 @ 100MHZ  [cc0603]
FB5  220 @ 100MHZ  [cc0603]
J5  DNI  [berg1x2]
J6  USB3_TYPEB_CONNECTOR  [GSB321131HR]
J7  DNI  [berg1x2]
J8  DNI  [berg1x2]
J9  DNI  [berg1x2]
J10  DNI  [berg1x2]
R77  0  [r0402]
R78  330  [r0402]
U7  TPD2EUSB30_DNI  [DRT_r-pdso-n3]
U8  TPD2EUSB30_DNI  [DRT_r-pdso-n3]
U9  TPD2EUSB30_DNI  [DRT_r-pdso-n3]

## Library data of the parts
C1-C7 C9-C19 C21-C53 C58-C60 C65-C67 = cc0402
C8 C20 = cc0603
J1 = Display_Port_Connector_Sink_0
R1 R11 R21-R24 R27-R30 R44 = r0603
R2-R10 R12-R20 R25 R26 R31-R43 R45-R56 = r0402
J2 = Display_Port_Connector_Source2
JMP1 = 3_Pin_Berg_Jumper_1
JMP2 = 3_Pin_Berg_Jumper
J3 = 5x2_Keyed_Connector
JMP3-JMP5 JMP8 JMP10 JMP11 = 4_Pin-T_Berg_Jumper
JMP6 JMP7 JMP9 = 2_Pin_Berg_Jumper
U1 = DP130_48_QFN_0
D1 D3 D5-D8 = LED_0603
U2 = ZXTD09N50DE6
C54 = PCap7343_68uf
C55 = PCap7343_10uf
C56 = NPCap1206_1.0uf
C57 C63 C64 = Tant_C_Cap_10uF
C61 C68 = Tant_D_Cap_220uF
C62 C69 = Tant_C_Cap_22uF
D2 = LED_HSMB: Mfr_Part_Number: HSMB-C170
D4 = BAT60A
J4 = Battery_Holder_9V
L1 L2 = Ferrite_Bead_1210_HI1206N10R-00
P1 = RAPC722: SILK: +9V
U3 = TPS74401
U4 = REG104
C70-C107 = CAP_NP
JP1-JP3 = eprt-head-00001-0000: Manufacturer: Berg; Manufacturer's Part#: 54101-T32-03; PART_NUMBER: HS_PORTIND; TI_Silktext: HS_PORTIND
JP4 = eprt-conn-00002-0000: Manuf: 3M; Manuf PN: 2510-6003UB; Manufacturer: 3M; Manufacturer's Part#: 2510-6003UB; PART_NUMBER: DRY2JTAG_3P3; Part#: eprt-conn-00002-0002; TI_Silktext: DRY2JTAG_3P3
R57 R60-R63 R65-R78 = R: Tolerance: 5%
R58 R59 R64 = R: Tolerance: 1%
SW1 = Light_Touch_Switch
U5 = TUSB8040_1: MFC: TEXAS INSTRUMENTS
U6 = TPS3809K33
Y1 = ECS-25MHZ
D9 = LED_HSMB: Mfr_Part_Number: HSMG-C170
FB1-FB5 = FERRITE_BEAD: FBEAD 1000@100MHz; Device: BEAD1806; MFC: MuRata; Manuf: MuRata; Manuf PN: BLM18EG221SN1D; Part Number: BLM18EG221SN1D; Part#: BLM18EG221SN1D
J5 J7-J10 = HDR2X1_M_.1
J6 = USB3_TYPEB_CONNECTOR_2: Manuf: Foxconn; Manuf PN: UEB11123-2JK1-4H; PART_NUMBER: USB3_UP0; TI_Silktext: USB3_UP0
U7-U9 = TPD2E009: Manuf PN: TPD2EUSB30DRT

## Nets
9V: C67.1 C68.1 C69.1 JMP11.2 U4.1(Vin) U4.5(Enable)
9V_BATT_IN: J4.1(P) JMP11.1
9V_DC_IN: D4.1(C) JMP11.3
9V_WALL_IN: D4.2(A) P1.3(TIP)
GND: C8.2 C20.2 C21.2 C22.2 C23.2 C24.2 C25.2 C26.2 C27.2 C28.2 C29.2 C30.2 C31.2 C32.2 C33.2 C34.2 C35.2 C36.2 C37.2 C38.2 C39.2 C40.2 C41.2 C42.2 C43.2 C44.2 C45.2 C46.2 C47.2 C48.2 C49.2 C50.2 C51.2 C52.2 C53.2 C54.2 C55.2 C56.2 C57.2 C58.2 C59.2 C60.2 C61.2 C62.2 C63.2 C64.2 C65.2 C66.2 C67.2 C68.2 C69.2 C72.2 C74.2 C76.2 C77.2 C78.2 C79.2 C80.2 C81.2 C82.2 C83.2 C84.2 C85.2 C86.2 C87.2 C88.2 C89.2 C90.2 C91.2 C92.2 C93.2 C94.2 C95.2 C96.2 C97.2 C98.2 C99.2 C100.2 C101.2 C102.2 C103.2 C104.2 C105.2 C106.2 C107.2 D2.1 D3.1 J1.2(GND1) J1.5(GND2) J1.8(GND3) J1.11(GND4) J1.16(GND6) J1.19(DP_PWR_RTN) J2.2(GND1) J2.5(GND2) J2.8(GND3) J2.11(GND4) J2.16(GND6) J2.19(RTN) J3.6 J4.2(N) J6.4(GND) J6.7(GND) JMP5.4 JMP7.2 JMP9.2 JMP11.4 JP4.2 JP4.4 JP4.6 JP4.8 JP4.10 P1.1(SLEEVE) R1.2 R2.1 R3.1 R10.2 R11.2 R13.2 R17.1 R19.2 R23.2 R24.2 R29.2 R30.2 R34.2 R49.2 R56.2 R59.2 R65.2 R66.2 R67.2 R68.2 R73.1 R74.1 R75.1 R76.2 R77.2 R78.2 SW1.1 SW1.2 SW1.5 U1.18(GND1) U1.24(GND2) U1.31(GND3) U1.49(THERMAL_PAD) U2.5(E2) U3.4(GND) U4.3(GND1) U4.6(GND2) U5.81(PAD) U6.1(GND) U7.3(GND) U8.3(GND) U9.3(GND)
GND_EARTH: C78.1 C79.1 J6.10(SHIELD0) J6.11(SHIELD1) R77.1
SGND1: C8.1 J1.21(GND7) J1.22(GND8) J1.23(GND9) J1.24(GND10) R1.1
SGND2: C20.1 J2.21(GND7) J2.22(GND8) J2.23(GND9) J2.24(GND10) R11.1
VCC_SS_VDD_DS: C30.1 C31.1 C32.1 C33.1 C34.1 C35.1 C36.1 R35.2 R36.2 U1.6(VCC2_SS_VDDD0_DS) U1.12(VCC3_SS_VDDD1_DS) U1.25(VCC4_SS_VDDD2_DS) U1.32(VCC5_SS_VDDD3_DS)
VDDD_1P05V: C22.1 C23.1 C24.1 C25.1 C26.1 C27.1 C28.1 C29.1 R37.1 U1.15(DNC0_SS_VDDD4_DS) U1.21(DNC1_SS_VDDD5_DS) U1.37(DNC2_SS_VDDD6_DS) U1.43(DNC3_SS_VDDD7_DS)
VDDD_DREG_PIN: C37.1 C38.1 C39.1 C40.1 R33.1 R39.2 R40.2 R41.1 U1.2(VDDD_DREG_SS_VDDD8_DS)
VDDD_REG: R39.1
1P05V: C41.1 C42.1 C43.1 C44.1 C45.1 C46.1 C57.1 C58.1 C59.1 FB4.2 FB5.2 J9.2 J10.2 JMP7.1 L1.2 R35.1 R37.2 R40.1 R42.1
1P05V_A: C104.1 C105.1 C106.1 C107.1 FB5.1 J10.1 U5.1(VDDA11)
1P05V_B: C91.1 C92.1 C93.1 C94.1 C95.1 C96.1 C97.1 C98.1 C99.1 C100.1 C101.1 C102.1 C103.1 FB4.1 J9.1 U5.5(VDD11) U5.10(VDD11) U5.11(VDD11) U5.16(VDD11) U5.20(VDD11) U5.26(VDD11) U5.32(VDD11) U5.37(VDD11) U5.42(VDD11) U5.46(VDD11) U5.51(VDD11) U5.52(VDD11) U5.57(VDD11) U5.61(VDD11) U5.62(VDD11) U5.67(VDD11) U5.71(VDD11)
1P05V_HIGH: JMP8.2 JMP8.4 R43.2 R45.2 R47.2 R49.1 U3.2(FB)
1P05V_LOW: JMP8.3 R48.2
1P05V_NOM: JMP8.1 R46.2
1P05V_REG: C54.1 C55.1 C56.1 L1.1 R43.1 R45.1 R46.1 R47.1 R48.1 U3.3(OUT)
3P3V: C47.1 C48.1 C49.1 C50.1 C51.1 C52.1 C53.1 C64.1 C65.1 C66.1 FB1.2 FB2.2 FB3.2 J5.2 J7.2 J8.2 JMP5.1 JMP9.1 L2.2 R5.1 R7.1 R8.1 R9.1 R12.1 R14.2 R18.2 R20.2 R21.1 R22.1 R27.1 R28.1 R36.1 R38.1 R44.1 R50.1 R60.2 R61.2 R62.2 R63.1 R69.1 R70.1 R71.1 R72.1 U1.1(VCC0_SS_AND_DS) U1.36(VCC1_SS_AND_DS) U3.5(IN) U3.6(BIAS) U6.3(VDD)
3P3V_A: C84.1 C85.1 C86.1 C87.1 C88.1 C89.1 C90.1 FB3.1 J8.1 U5.4(VDDA33) U5.19(VDDA33) U5.43(VDDA33) U5.58(VDDA33) U5.68(VDDA33) U5.80(VDDA33)
3P3V_B: C80.1 C81.1 C82.1 C83.1 FB2.1 J7.1 U5.21(VDD33) U5.38(VDD33) U5.72(VDDR33)
3P3V_HIGH: JMP10.2 JMP10.4 R51.2 R52.2 R54.2 R56.1 U4.4(NR/Adjust)
3P3V_LOW: JMP10.3 R55.2
3P3V_NOM: JMP10.1 R53.2
3P3V_OSC: C76.1 C77.1 FB1.1 J5.1 U5.77(VDDA33_OSC)
3P3V_REG: C61.1 C62.1 C63.1 L2.1 R51.1 R52.1 R53.1 R54.1 R55.1 U4.2(Vout)
/DREG_LED: D1.1 U2.3(C2)
/DREG_LED_PU: D1.2 R38.2
ADDR_EQ: JMP3.2 U1.3(ADDR)
ADDR_EQ_MID: JMP3.4 R21.2 R23.1
ADDR_EQ_PD: JMP3.3 R24.1
ADDR_EQ_PU: JMP3.1 R22.2
AUX_N_SDA_IN: C11.1 J1.17(AUX_n_(SDA)) R6.1
AUX_P_SCL_IN: C10.1 J1.15(AUX_p_(SCL)) R4.1
AUX_SINK_N: R16.1 U1.27(AUX_SNKn)
AUX_SINK_OUTPUT_N: J2.17(AUX_n) R14.1 R16.2
AUX_SINK_OUTPUT_P: J2.15(AUX_p) R15.2 R17.2
AUX_SINK_P: R15.1 U1.28(AUX_SNKp)
AUXSCL_SOURCE_P: C10.2 U1.30(AUX_SRCp)
AUXSDA_SOURCE_N: C11.2 U1.29(AUX_SRCn)
BATDIS: JP3.3 R75.2
BATEN: JP3.1 R62.1
CAD: JMP1.2 U1.10(CAD_SINK_(In))
CAD_SINK: J2.13(CAD) JMP1.3 R13.1
CAP_UP_TXM: C73.1 J6.5(SSTXN) U7.1(D+)
CAP_UP_TXP: C75.1 J6.6(SSTXP) U7.2(D-)
CEC: J1.14(DP_CEC_(GND)) J2.14(GND5) R9.2 R10.1
DP0_N: C13.1 U1.22(OUT0n)
DP0_P: C12.1 U1.23(OUT0p)
DP1_N: C15.1 U1.19(OUT1n)
DP1_P: C14.1 U1.20(OUT1p)
DP2_N: C17.1 U1.16(OUT2n)
DP2_P: C16.1 U1.17(OUT2p)
DP3_N: C19.1 U1.13(OUT3n)
DP3_P: C18.1 U1.14(OUT3p)
DP_CAD_SINK_OUTPUT: J1.13(CAD_(GND)) R3.2 U1.8(CAD_SRC_(Out))
DP_HPD_SINK_OUTPUT: J1.18(HPD) R2.2 U1.9(HPD_SRC_(Out))
DP_OUTPUT_0_N: C13.2 J2.3(ML_0n)
DP_OUTPUT_0_P: C12.2 J2.1(ML_0p)
DP_OUTPUT_1_N: C15.2 J2.6(ML_1n)
DP_OUTPUT_1_P: C14.2 J2.4(ML_1p)
DP_OUTPUT_2_N: C17.2 J2.9(ML_2n)
DP_OUTPUT_2_P: C16.2 J2.7(ML_2p)
DP_OUTPUT_3_N: C19.2 J2.12(ML_3n)
DP_OUTPUT_3_P: C18.2 J2.10(ML_3p)
DP_PWR_SINK: J1.20(DP_PWR) R5.2
DREG_LED_BASE: R41.2 U2.4(B2)
EN_EQ: JMP4.2 U1.26(---------_EN)
EN_MID: JMP4.4 R27.2 R29.1
EN_PD: JMP4.3 R30.1
EN_PU: JMP4.1 R28.2
FULLPWRMGMTZ_SMBA1: JP1.2 U5.41(FULLPWRMGMTZ_SMBA1)
HPD: JMP2.2 U1.11(HPD_SINK_(IN))
HPD_OVERIDE: JMP2.1 R18.1
HPD_SINK: J2.18(HPD) JMP2.3 R19.1
HS: D5.2 U5.22(HS)
HS_SUSPEND: D7.2 U5.24(HS_SUSPEND)
I2C: JP2.1 R61.1
I2C_PWR: J3.5 JMP5.3
LOCAL_I2C_PULLUP: JMP5.2 R31.1 R32.1
LOCAL_SCL: J3.9 R25.2 R31.2 U1.4(SCL_CTL)
LOCAL_SDA: J3.10 R26.2 R32.2 U1.5(SDA_CTL)
MAIN_LINK_0N: C7.2 U1.39(IN0n)
MAIN_LINK_0P: C9.2 U1.38(IN0p)
MAIN_LINK_1N: C5.2 U1.42(IN1n)
MAIN_LINK_1P: C6.2 U1.41(IN1p)
MAIN_LINK_2N: C3.2 U1.45(IN2n)
MAIN_LINK_2P: C4.2 U1.44(IN2p)
MAIN_LINK_3N: C1.2 U1.48(IN3n)
MAIN_LINK_3P: C2.2 U1.47(IN3p)
MAIN_LINK_IN_0N: C7.1 J1.10(ML_0n)
MAIN_LINK_IN_0P: C9.1 J1.12(ML_0p)
MAIN_LINK_IN_1N: C5.1 J1.7(ML_1n)
MAIN_LINK_IN_1P: C6.1 J1.9(ML_1p)
MAIN_LINK_IN_2N: C3.1 J1.4(ML_2n)
MAIN_LINK_IN_2P: C4.1 J1.6(ML_2p)
MAIN_LINK_IN_3N: C1.1 J1.1(ML_3n)
MAIN_LINK_IN_3P: C2.1 J1.3(ML_3p)
PWRON0Z_BATEN0: JP3.2 U5.39(PWRON0Z_BATEN0)
RSTN: C21.1 JMP6.1 R33.2 U1.35(------------_RSTN)
SCL_SMBCLK: R25.1 U5.34(SCL_SMBCLK)
SCL_SOURCE: R4.2 R7.2 U1.33(-------__SCL_DDC)
SDA_SMBDAT: R26.1 U5.35(SDA_SMBDAT)
SDA_SOURCE: R6.2 R8.2 U1.34(-------__SDA_DDC)
SMBUS: JP2.3 R74.2
SMBUSZ: JP2.2 U5.36(SMBUSZ)
SS: D6.2 U5.23(SS)
SS_SUSPEND: D8.2 U5.25(SS_SUSPEND)
TCK: JP4.9 R69.2 U5.27(JTAG_TCK)
TDI: JP4.5 R71.2 U5.31(JTAG_TDI)
TDO: JP4.3 R72.2 U5.29(JTAG_TDO)
TMDS_CAD_OVERIDE: JMP1.1 R12.2
TMS: JP4.7 R70.2 U5.28(JTAG_TMS)
TRSTZ: JP4.1 R76.1 U5.30(JTAG_TRSTZ)
U1_VBUS: R58.1 R59.1 U5.73(USB_VBUS)
USB_DM_UP: J6.2(DM) U5.69(USB_DM_UP) U9.1(D+)
USB_DP_UP: J6.3(DP) U5.70(USB_DP_UP) U9.2(D-)
USB_SSRXM_UP: J6.8(SSRXN) U5.65(USB_SSRXM_UP) U8.1(D+)
USB_SSRXP_UP: J6.9(SSRXP) U5.66(USB_SSRXP_UP) U8.2(D-)
USB_SSTXM_UP: C73.2 U5.63(USB_SSTXM_UP)
USB_SSTXP_UP: C75.2 U5.64(USB_SSTXP_UP)
USB_VBUS_UP: C74.1 D9.2 J6.1(VBUS) R58.2
N16815626: D2.2 R42.2
N16816313: D3.2 R50.2
N16895248: J2.20(DP_PWR) R20.1
N17028916: R44.2 U3.7(EN)
N17031787: C60.1 U3.1(SS)
N17076688: JMP6.2 R34.1
N17110048: C71.1 R57.2 U5.76(XI) Y1.3(a3)
N17110064: C70.1 R57.1 U5.74(XO) Y1.1(a1)
N17110088: C70.2 C71.2 U5.75(VSS_OSC)
N17110472: D5.1 R65.1
N17110474: D6.1 R66.1
N17110476: D7.1 R67.1
N17110478: D8.1 R68.1
N17110576: R64.1 U5.79(USBR1_RTN)
N17110704: JP1.3 R73.2
N17110710: R64.2 U5.78(USB_R1)
N17110995: JP1.1 R60.1
N17111299: C72.1 R63.2 SW1.3 SW1.4 U5.33(GRSTz) U6.2(RESETZ)
N17116289: D9.1 R78.1

Not connected (* = marked no-connect by the designer): J3 1* 2* 3* 4* 7* 8*; P1 2(SHUNT)*; U1 7(NC1)* 40(NC2)* 46(NC3)*; U2 1(C1)* 2(E1)* 6(B1)*; U5 2(USB_DP_DN0)* 3(USB_DM_DN0)* 6(USB_SSRXP_DN0)* 7(USB_SSRXM_DN0)* 8(USB_SSTXP_DN0)* 9(USB_SSTXM_DN0)* 12(USB_SSRXP_DN2)* 13(USB_SSRXM_DN2)* 14(USB_SSTXP_DN2)* 15(USB_SSTXM_DN2)* 17(USB_DP_DN2)* 18(USB_DM_DN2)* 40(OVERCUR0Z)* 44(USB_DM_DN3)* 45(USB_DP_DN3)* 47(USB_SSRXP_DN3)* 48(USB_SSRXM_DN3)* 49(USB_SSTXP_DN3)* 50(USB_SSTXM_DN3)* 53(USB_SSRXP_DN1)* 54(USB_SSRXM_DN1)* 55(USB_SSTXP_DN1)* 56(USB_SSTXM_DN1)* 59(USB_DM_DN1)* 60(USB_DP_DN1)*; Y1 2(a2) 4(a4)

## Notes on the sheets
sheet 1
- NOTES:
  1.  SILKSCREEN ALL JUMPERS AND HEADERS.
  2.  PLACE ALL PARTS ON A 0 OR 90 DEGREE ORIENTATION.
  3.  HIGH SPEED SERIAL DATA SHOULD BE ROUTED AS SINGLE-ENDED 50 OHM TRANSMISSION LINES.  ROUTING DISTANCE SHOULD BE 3 INCHES OR LESS.
  4.  USE FR4-370 MATERIAL.
  5.  PLACE TI LOGO IN TOP SIDE METAL
- Texas Instruments and its subsidiaries (TI) reserve the right to make changes to their products and publications or to
  discontinue any product or service without notice, and advise customers to obtain the latest version of relevant
  information to verify, before placing orders, that information being relied on is current and complete.  All products are
  sold subject to the terms and conditions of sale supplied at the time of order acknowledgment, including those pertaining
  to warranty, patent infringement, and limitation of liability.
  Customers are responsible for their applications using TI components.  In order to minimize risks associated with
  applications using TI components, adequate design and operating safeguards must be provided by the customer to minimize
  inherent or procedural hazards.  The information in this document is provided by TI as a courtesy and in no way
  constitutes a reference design.  Any direct duplication of this design in its entirety is strictly prohibited without
  expressed written approval by TI.  Furthermore, TI assumes no liability for applications assistance or customer product
  design.  TI does not warrant or represent that any license, either express or implied, is granted under any patent right,
  copyright, mask work right, or other intellectual property right of TI covering or relating to any combination, machine,
  or process in which such semiconductor products or services might be or are used.  TI’s publication or information
  regarding any third party’s products or services does not constitute TI’s approval, warranty or endorsement thereof.
  Copyright © 2009.  Texas Instruments Incorporated
- DP130 DATA SHEET REVISION:  0.98
  DATA SHEET LAST UPDATED ON:  03/30/10
sheet 2
- DP Power does not normall get connected in the DP cable
- R4 and R6 can be installed when CAD is high allowing
  SCL/SDA to be routed to the input of the DP130
sheet 3
- SILKSCREEN
- OVRD
- CAD_OVRD
- NORM
- SILKSCREEN
- NOTE:  HPD OVERRIDE
     SHORT 2->3 FOR NORMAL HPD
     SHORT 1->2 FOR FORCED HPD (HIGH)
- HPD_OVRD
- OVRD
- NORM
- R20 can be installed to provide DP source power for
  dongle support
sheet 4
- SILKSCREEN
- ADDR_EQ_PU
- ADDR_EQ
- ADDR_EQ_MID
- ADDR_EQ_PD
- SILKSCREEN
- 3P3V
- SILKSCREEN
- I2C PULLUP
- GND
- I2C HEADER PWR
- EN_PU
- EN_MID
- EN
- EN_PD
- NOTE: RSTN is a 1.05V circuit.
  Do not drive this input more than the spec of 1.2V
- SILKSCREEN
- ENABLE
- RST_N
sheet 5
- SEE INSTALL/DNI NOTE
- SEE INSTALL/DNI NOTE
- SEE INSTALL/DNI NOTE
- PLACE NEAR THE DP130 DEVICE.
- PLACE NEAR THE DP130 DEVICE.
- SEE INSTALL/DNI NOTE
- SEE INSTALL/DNI NOTE
- PLACE NEAR THE DP130 DEVICE.
- INSTALL/DNI NOTE for DP130 SS/DS devices
       DP130-SS:
            INSTALL 0 ohm R36, R39
            DNI R35, R40, R37
       DP130-DS:
            INSTALL 0 ohm R35, R40, R37
            DNI R36, R39
- LOCAL DECOUPLING CAPACITORS.  PLACE NEAR THE DP130 DEVICE.
sheet 6
- 1.05V_NOM
- NOTE:  PLACE BULK DECOUPLING CAPACITORS
  NEAR THE REGULATORS AND FERRITE BEADS.
- SILKSCREEN
- 1.05V_HIGH
- 1.05V_LOW
- NOTE:  REMOVE R45 IF JMP8 IS INSTALLED.
- 3P3V_NOM
- NOTE:  PLACE BULK DECOUPLING CAPACITORS
  NEAR THE REGULATORS AND FERRITE BEADS.
- SILKSCREEN
- 3P3V_HIGH
- 3P3V_LOW
- NOTE:  REMOVE R52 IF JMP10 IS INSTALLED.
- SILKSCREEN
- BATT
- GND
- 9V
- WALL
sheet 7
- USB_DP_DN1
- USB_DM_DN1
- USB_SSRXP_DN1
- USB_DP_DN0
- USB_SSRXM_DN1
- USB_DM_DN0
- USB_SSTXP_DN1
- USB_SSRXP_DN0
- USB_SSTXM_DN1
- USB_SSRXM_DN0
- USB_SSTXP_DN0
- USB_SSTXM_DN0
- USB_DM_DN3
- USB_DP_DN3
- USB_SSRXP_DN3
- SILKSCREEN
- USB_DP_DN2
- USB_SSRXM_DN3
- USB_DM_DN2
- USB_SSTXP_DN3
- USB_SSRXP_DN2
- USB_SSTXM_DN3
- ENABLE
- USB_SSRXM_DN2
- USB_SSTXP_DN2
- PWR_MGMT
- USB_SSTXM_DN2
- DISABLE
- I2C
- OVERCUR0Z
- SMBUSZ
- SMBUS
- ENABLE
- BATEN
- DISABLE
- JTAG is for lab evaluation only.
  The customer can leave these
  pins unconnected.
sheet 8
- Optional ESD Protection
